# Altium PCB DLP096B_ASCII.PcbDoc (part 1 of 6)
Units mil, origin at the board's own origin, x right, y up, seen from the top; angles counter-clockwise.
Board outline 4950 x 3159.45 mil, 8 copper layers (Top Layer, GND1, SIGNAL1, POWER1, POWER2, SIGNAL2, GND2, Bottom Layer), stack 60.4 mil thick; 327 components, 222 nets, 1374 pads, 853 vias.
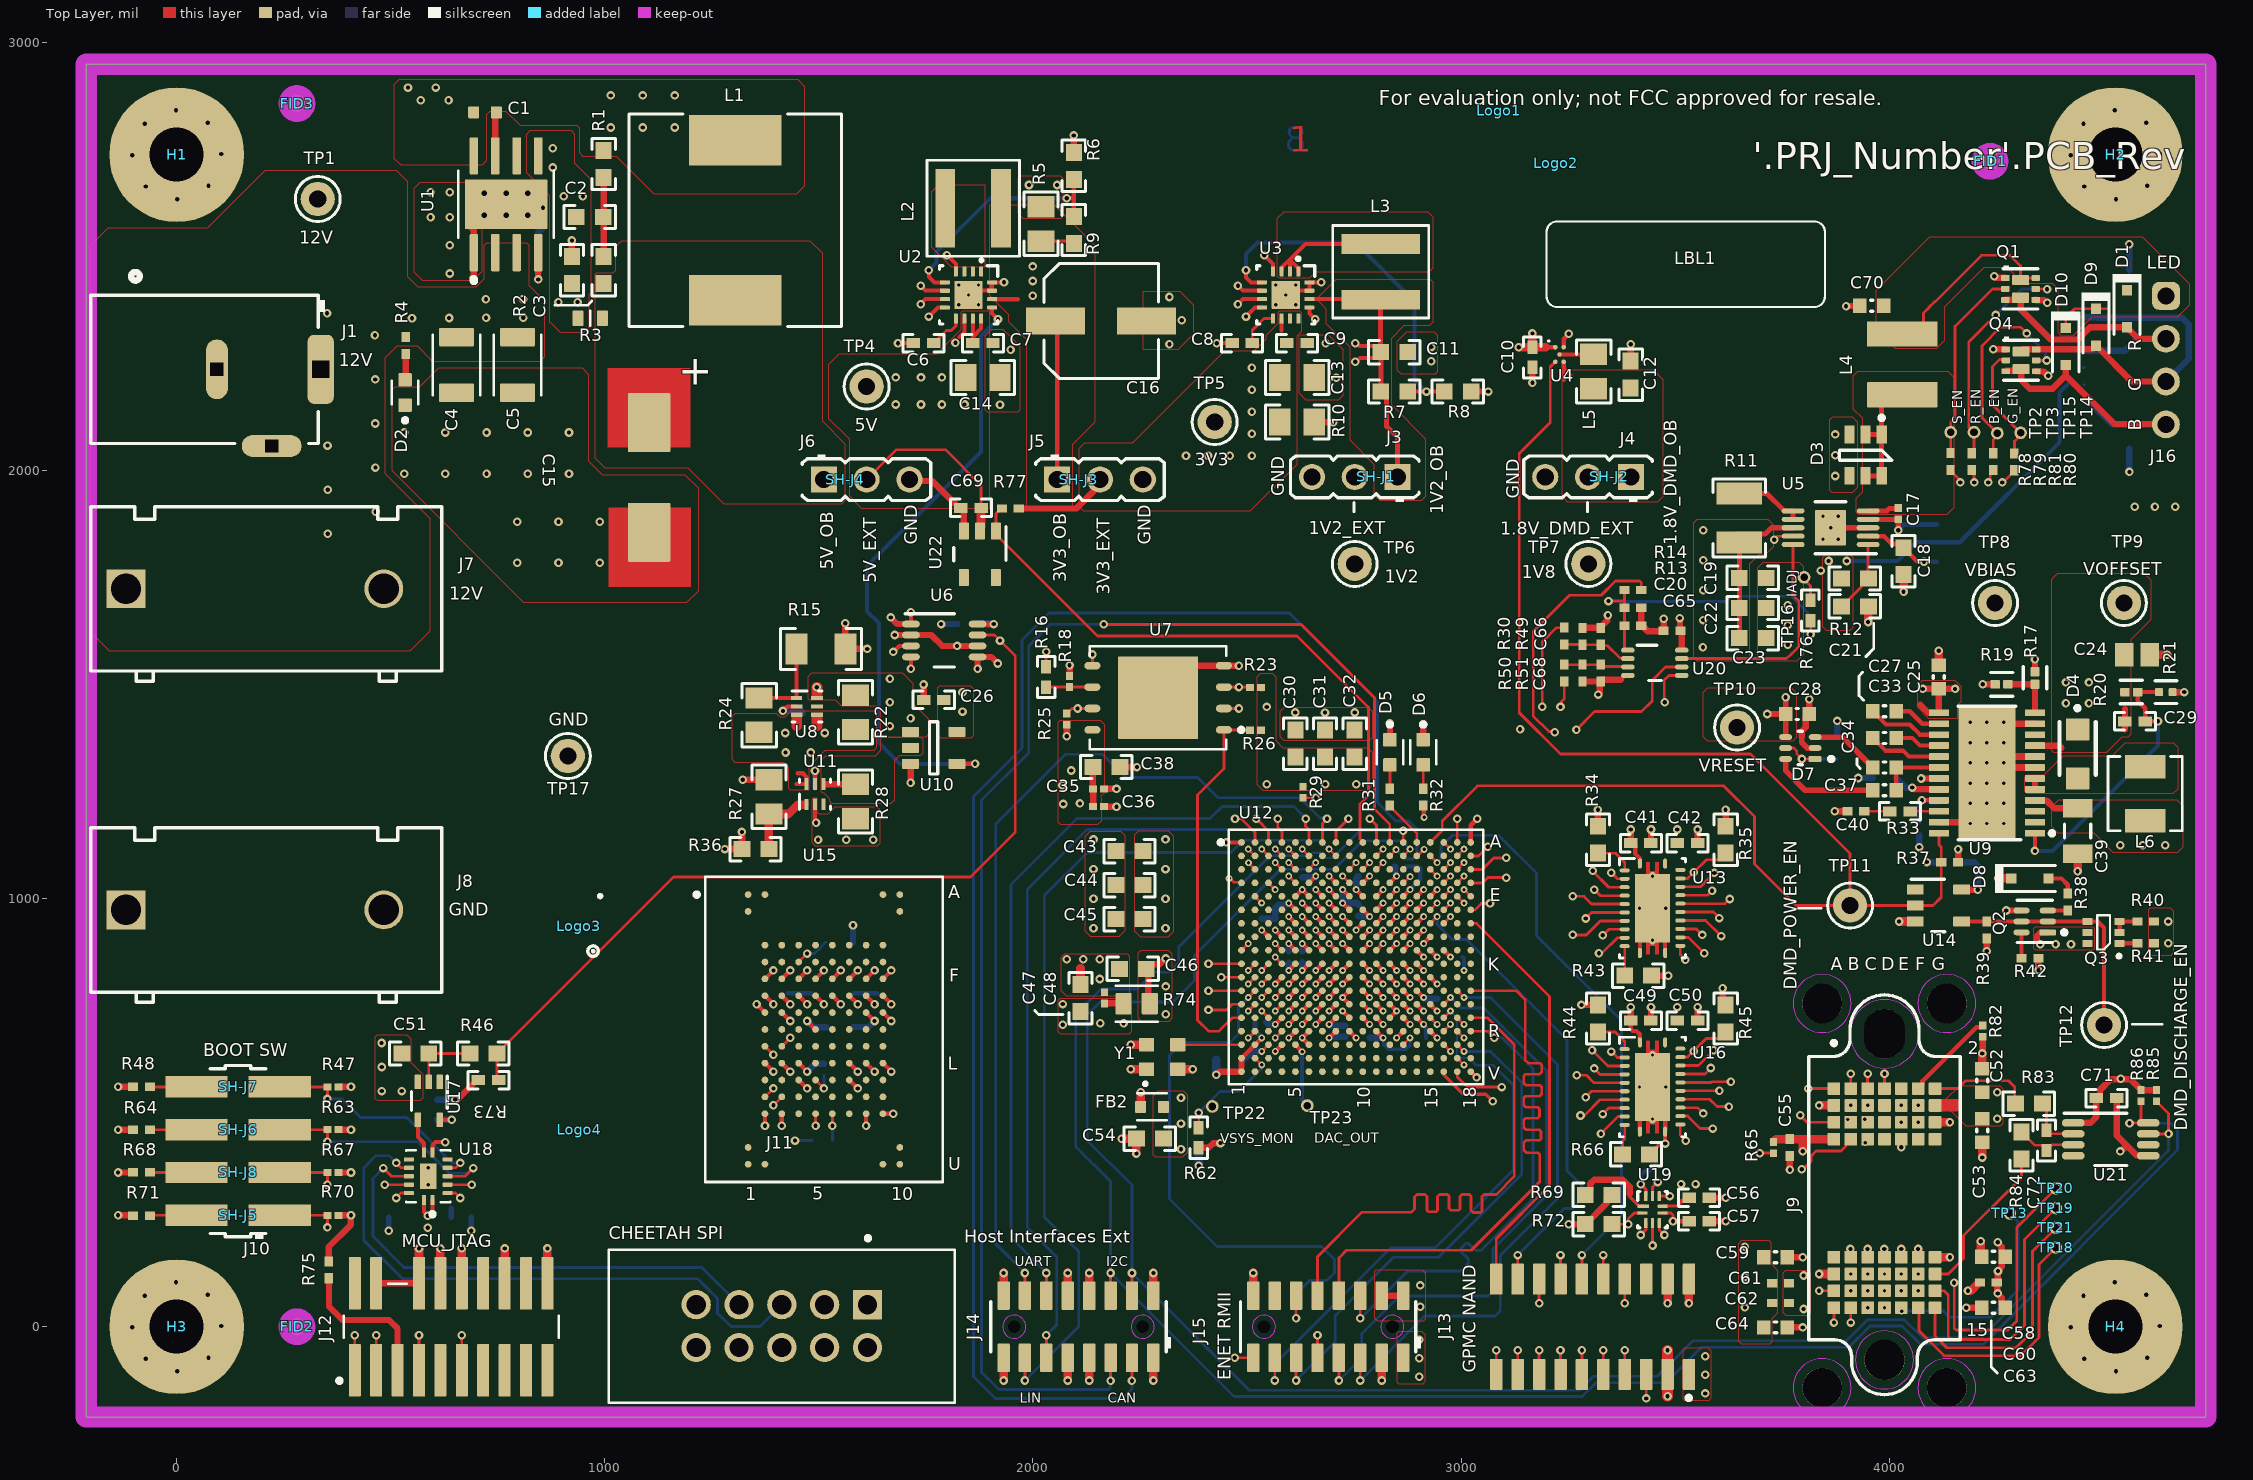
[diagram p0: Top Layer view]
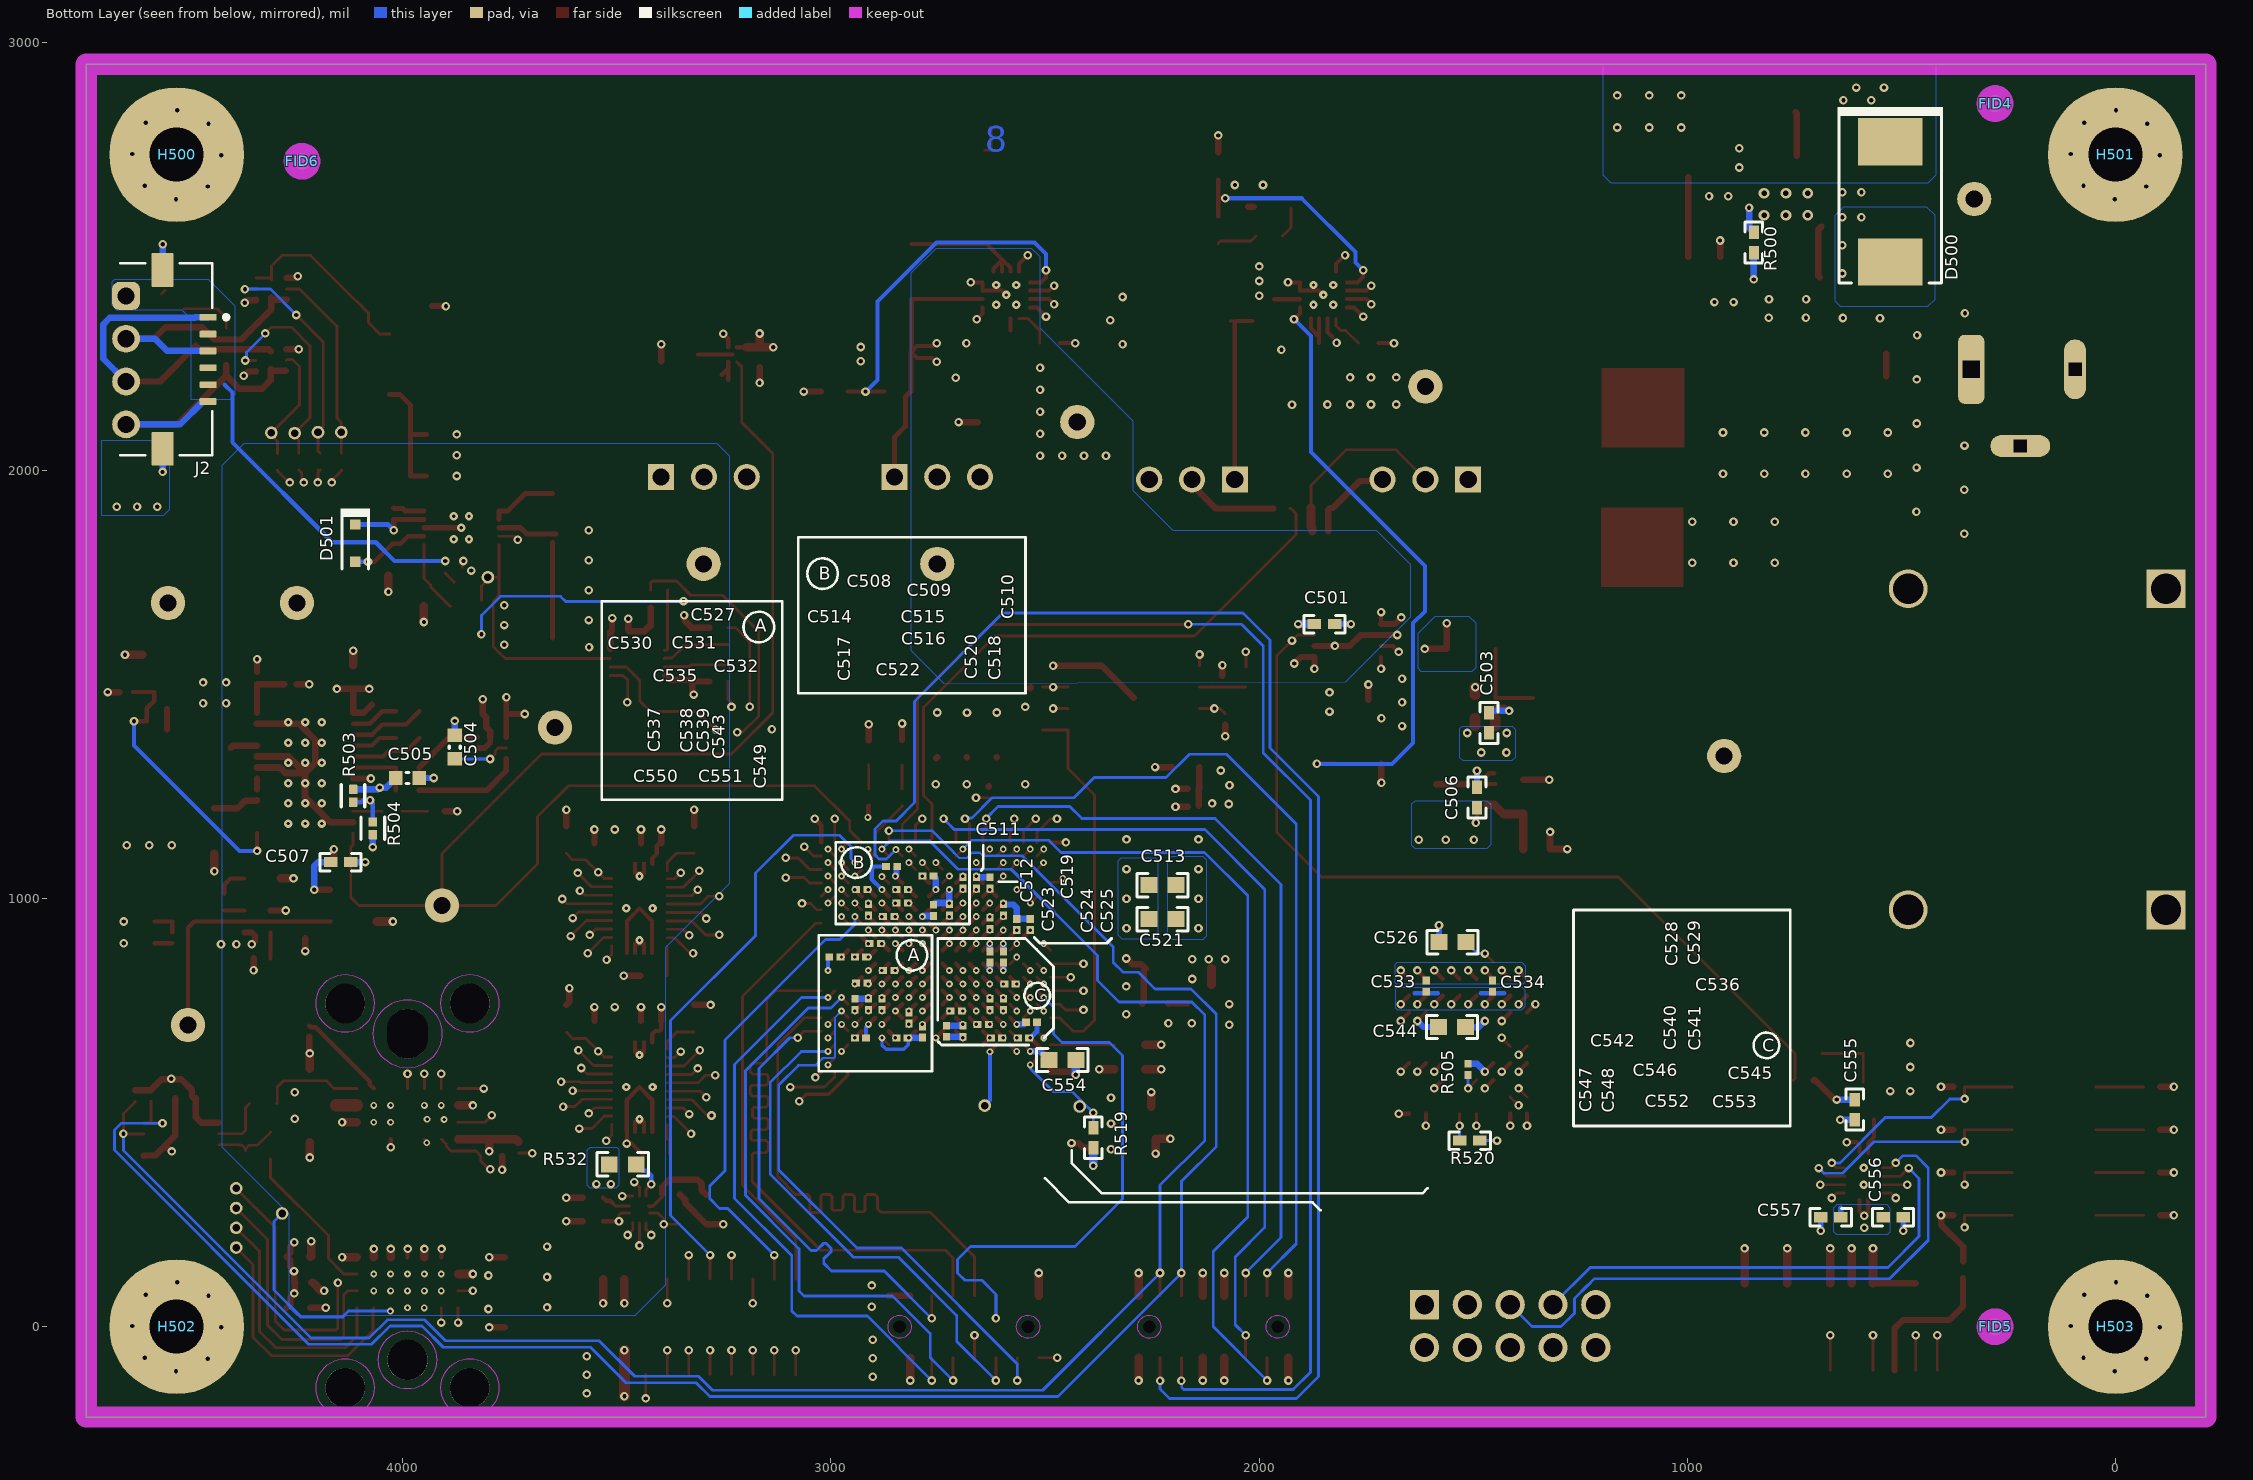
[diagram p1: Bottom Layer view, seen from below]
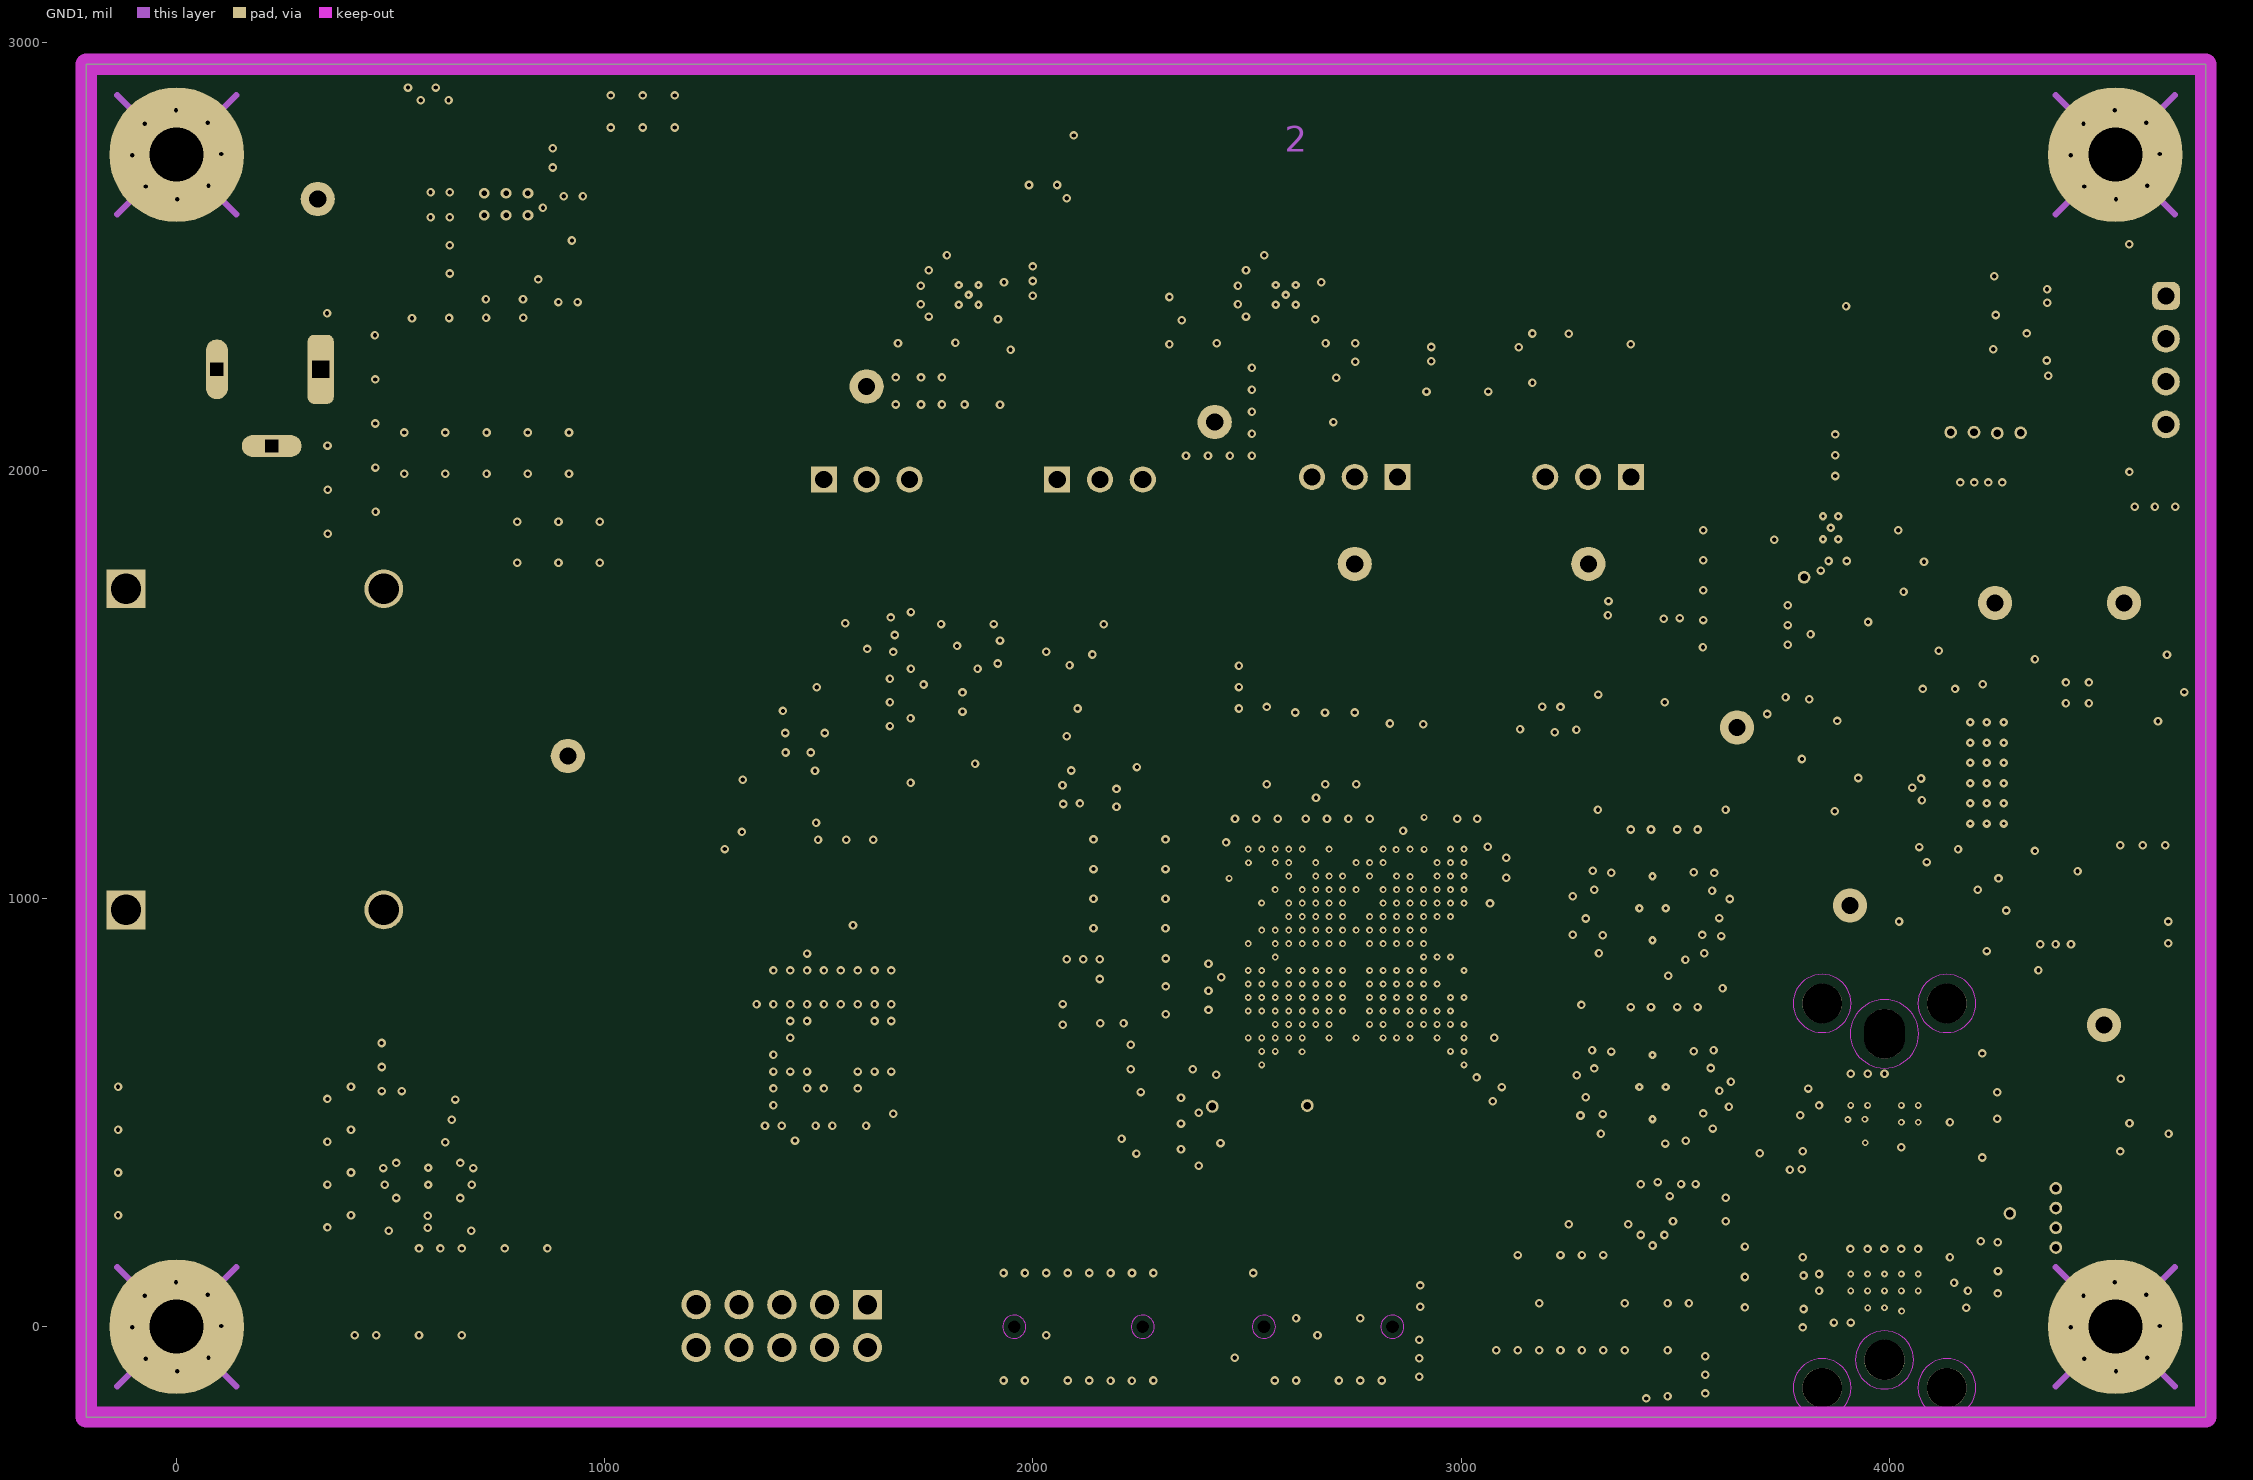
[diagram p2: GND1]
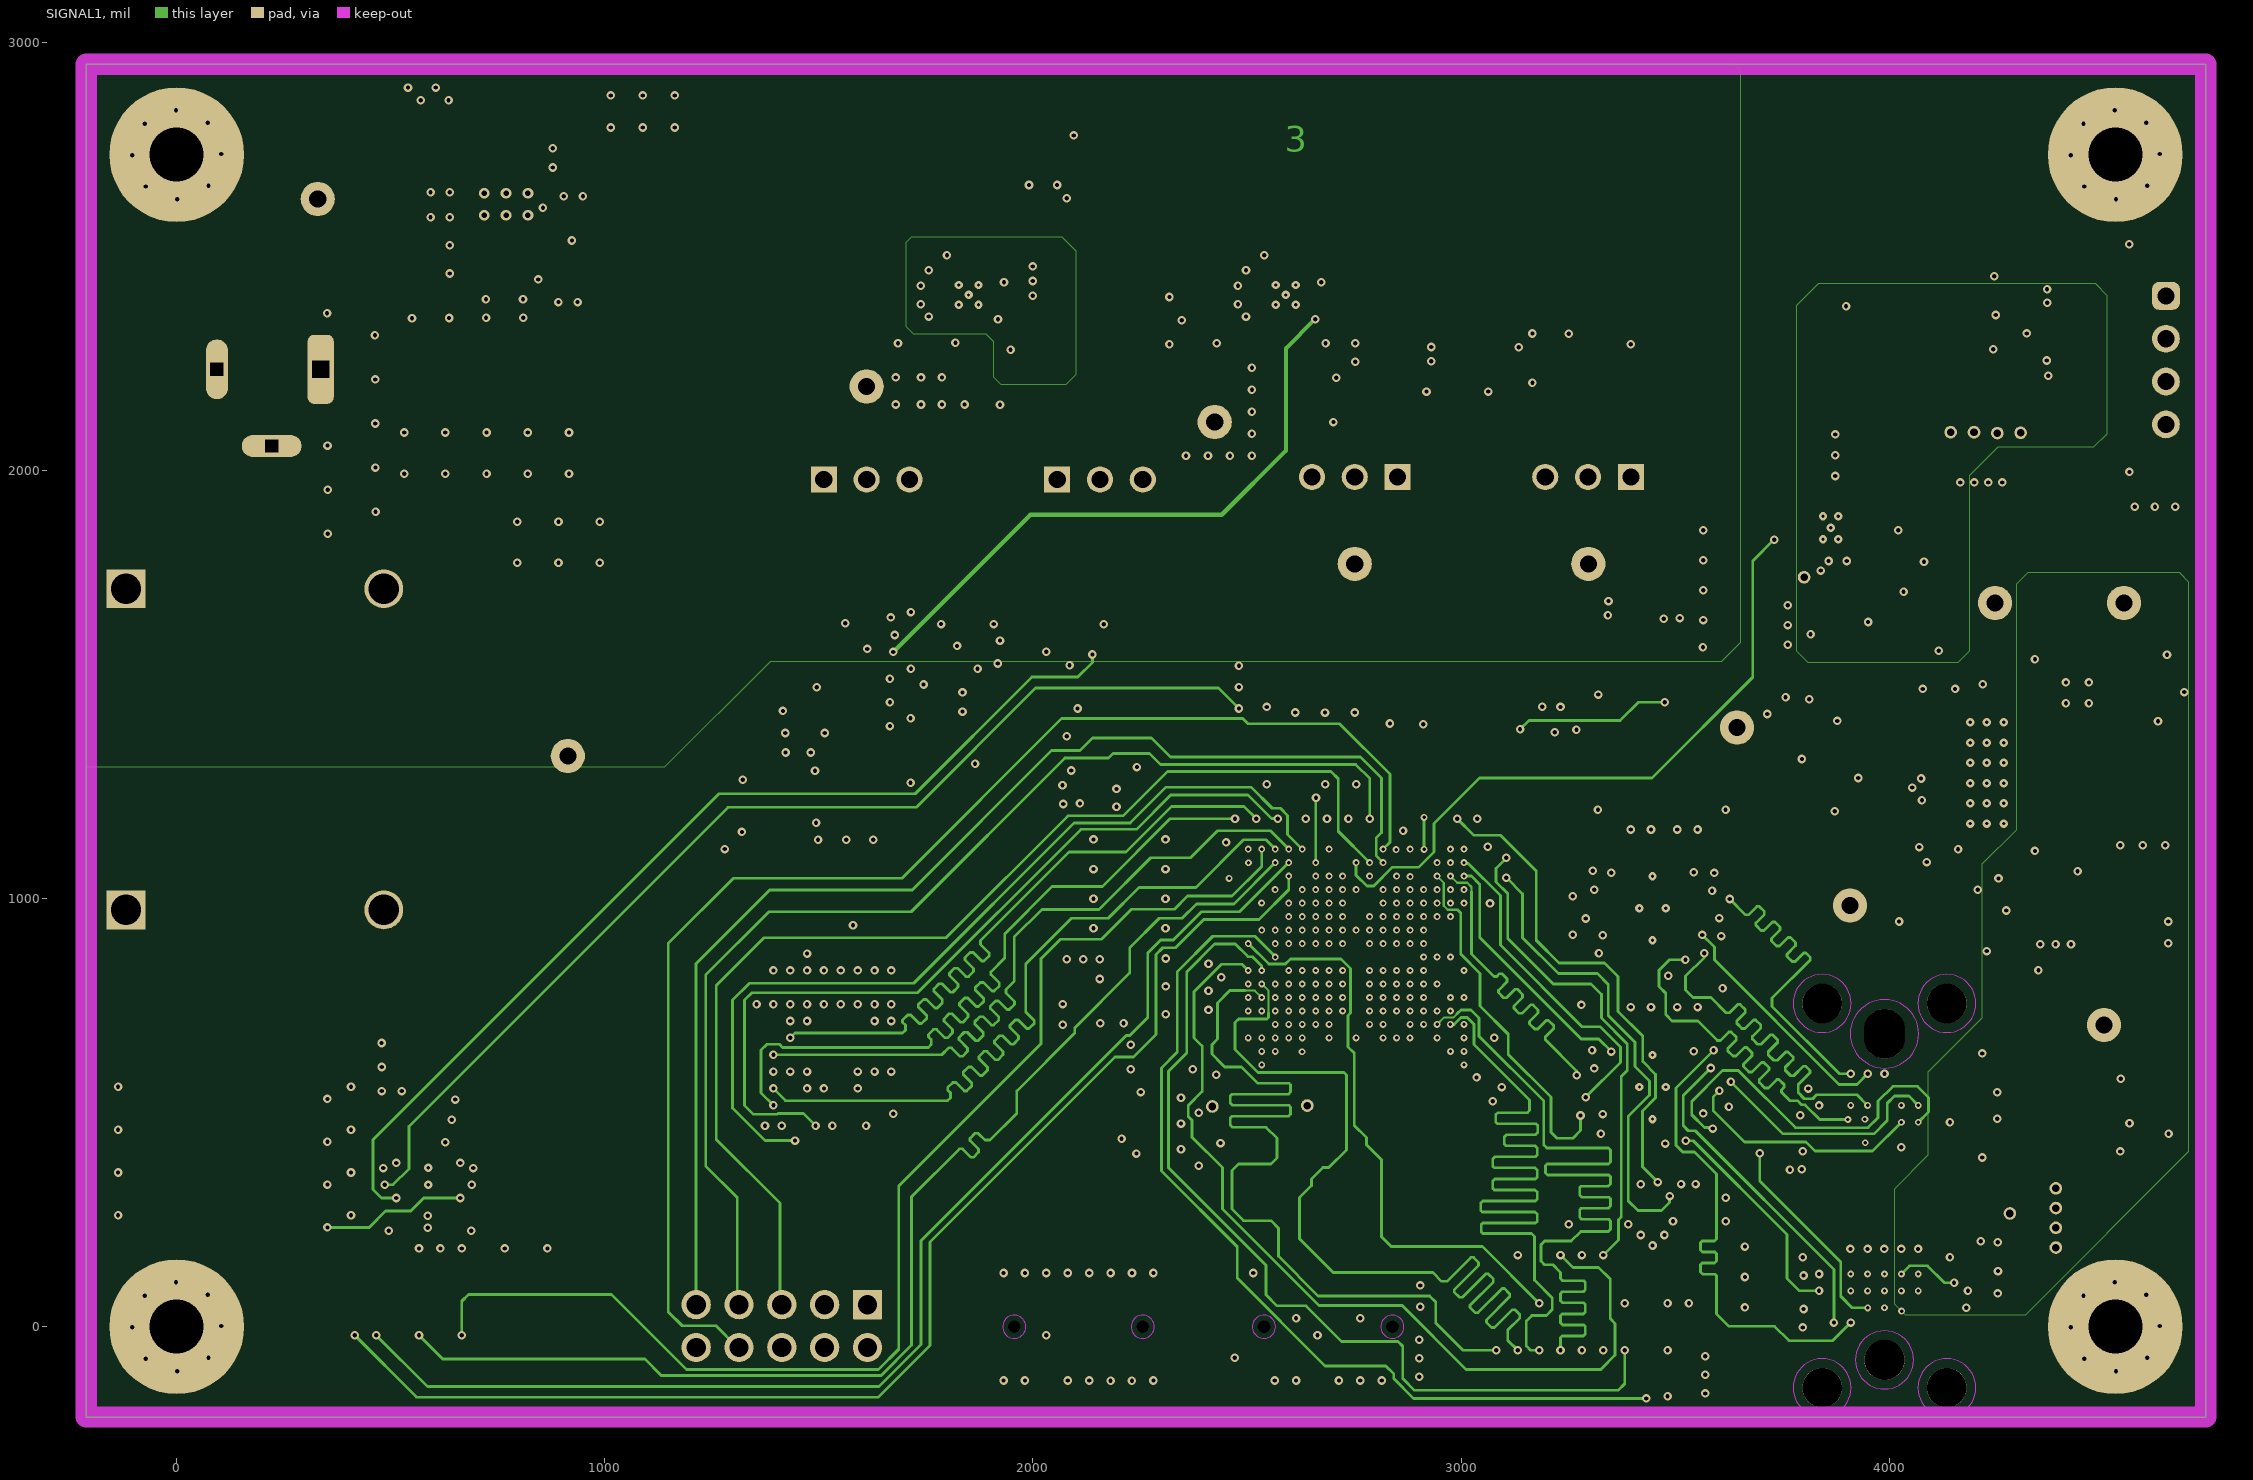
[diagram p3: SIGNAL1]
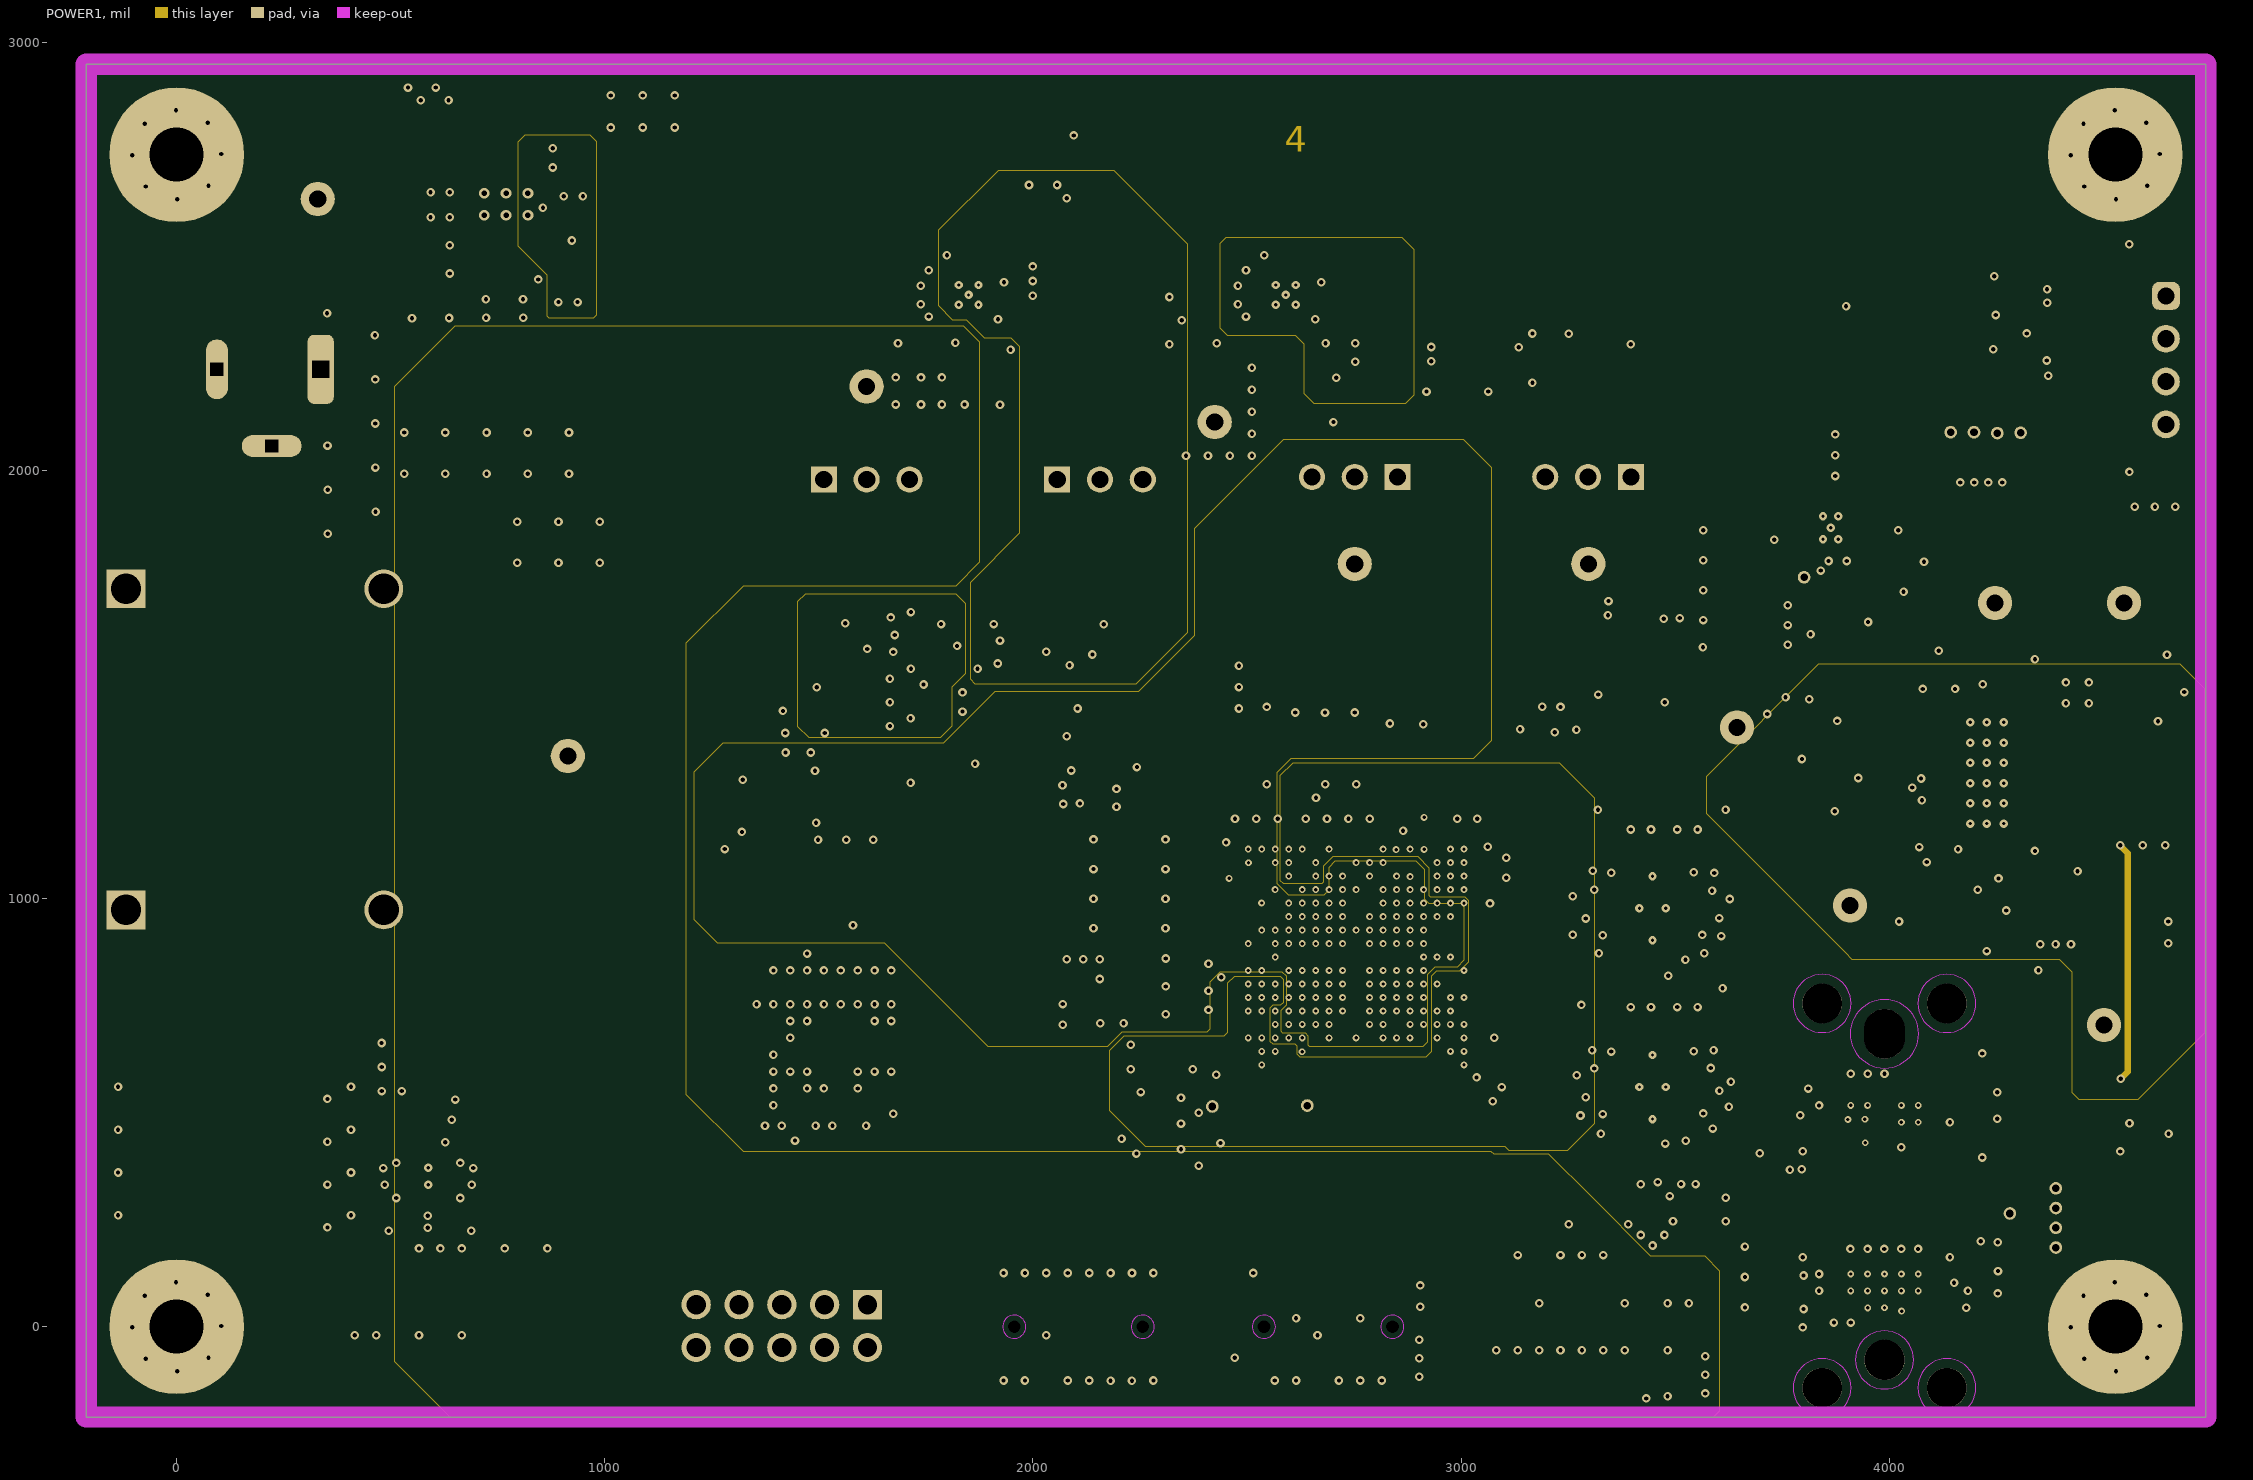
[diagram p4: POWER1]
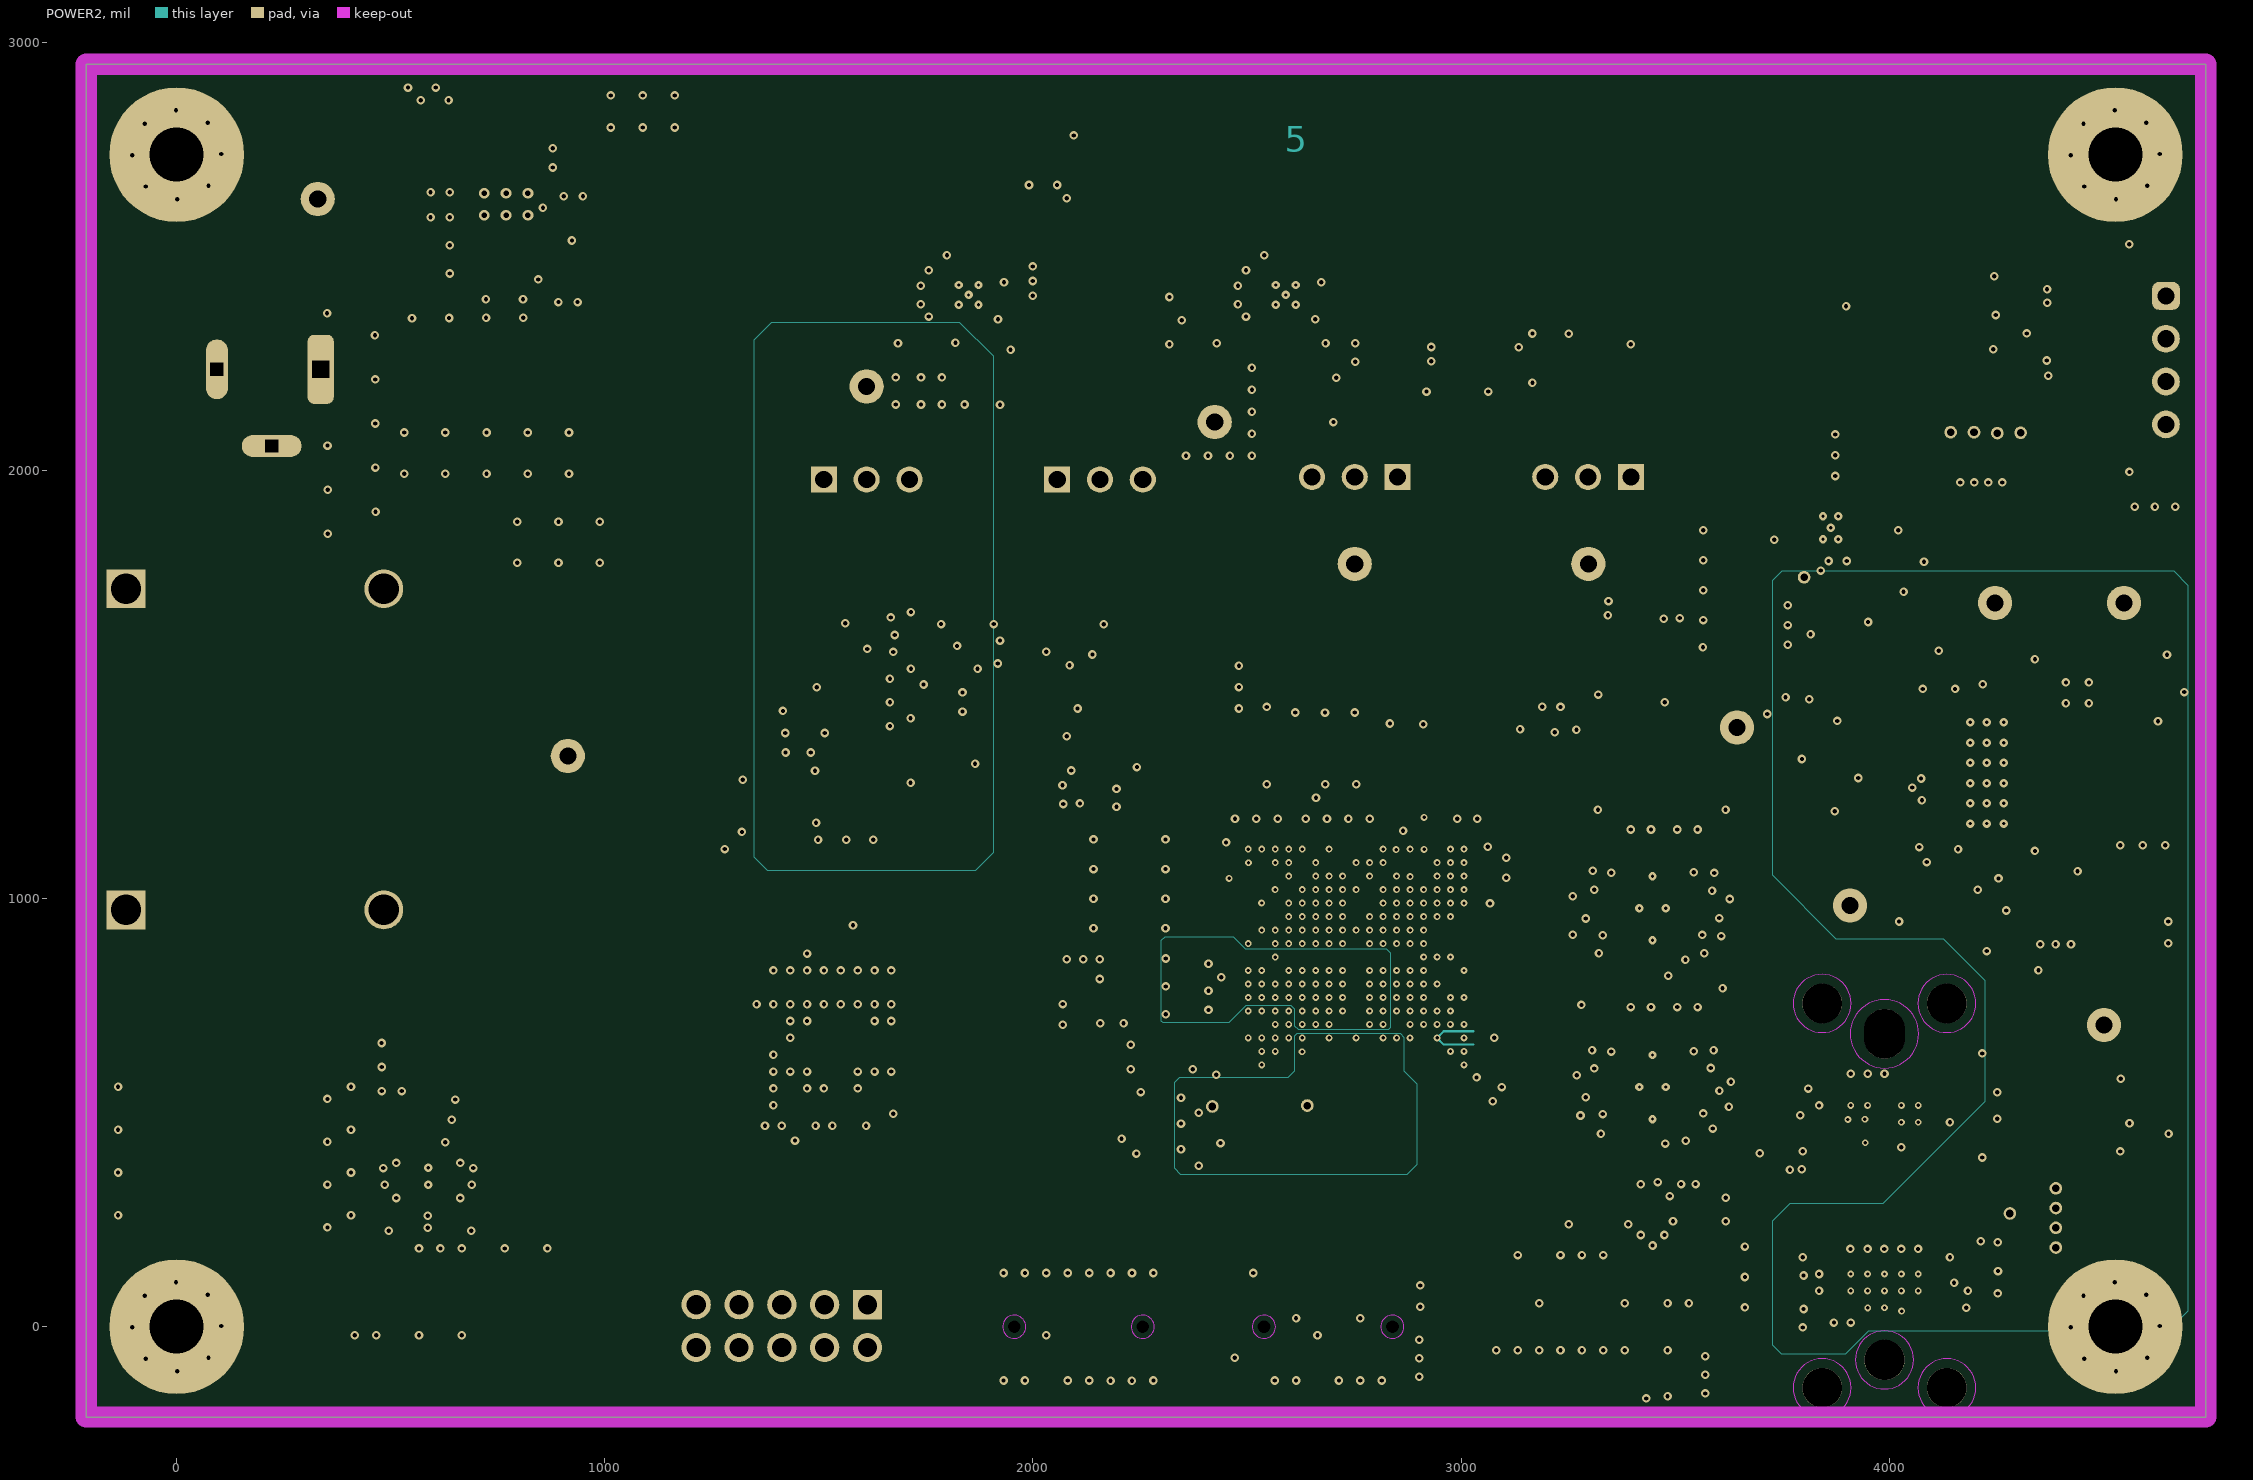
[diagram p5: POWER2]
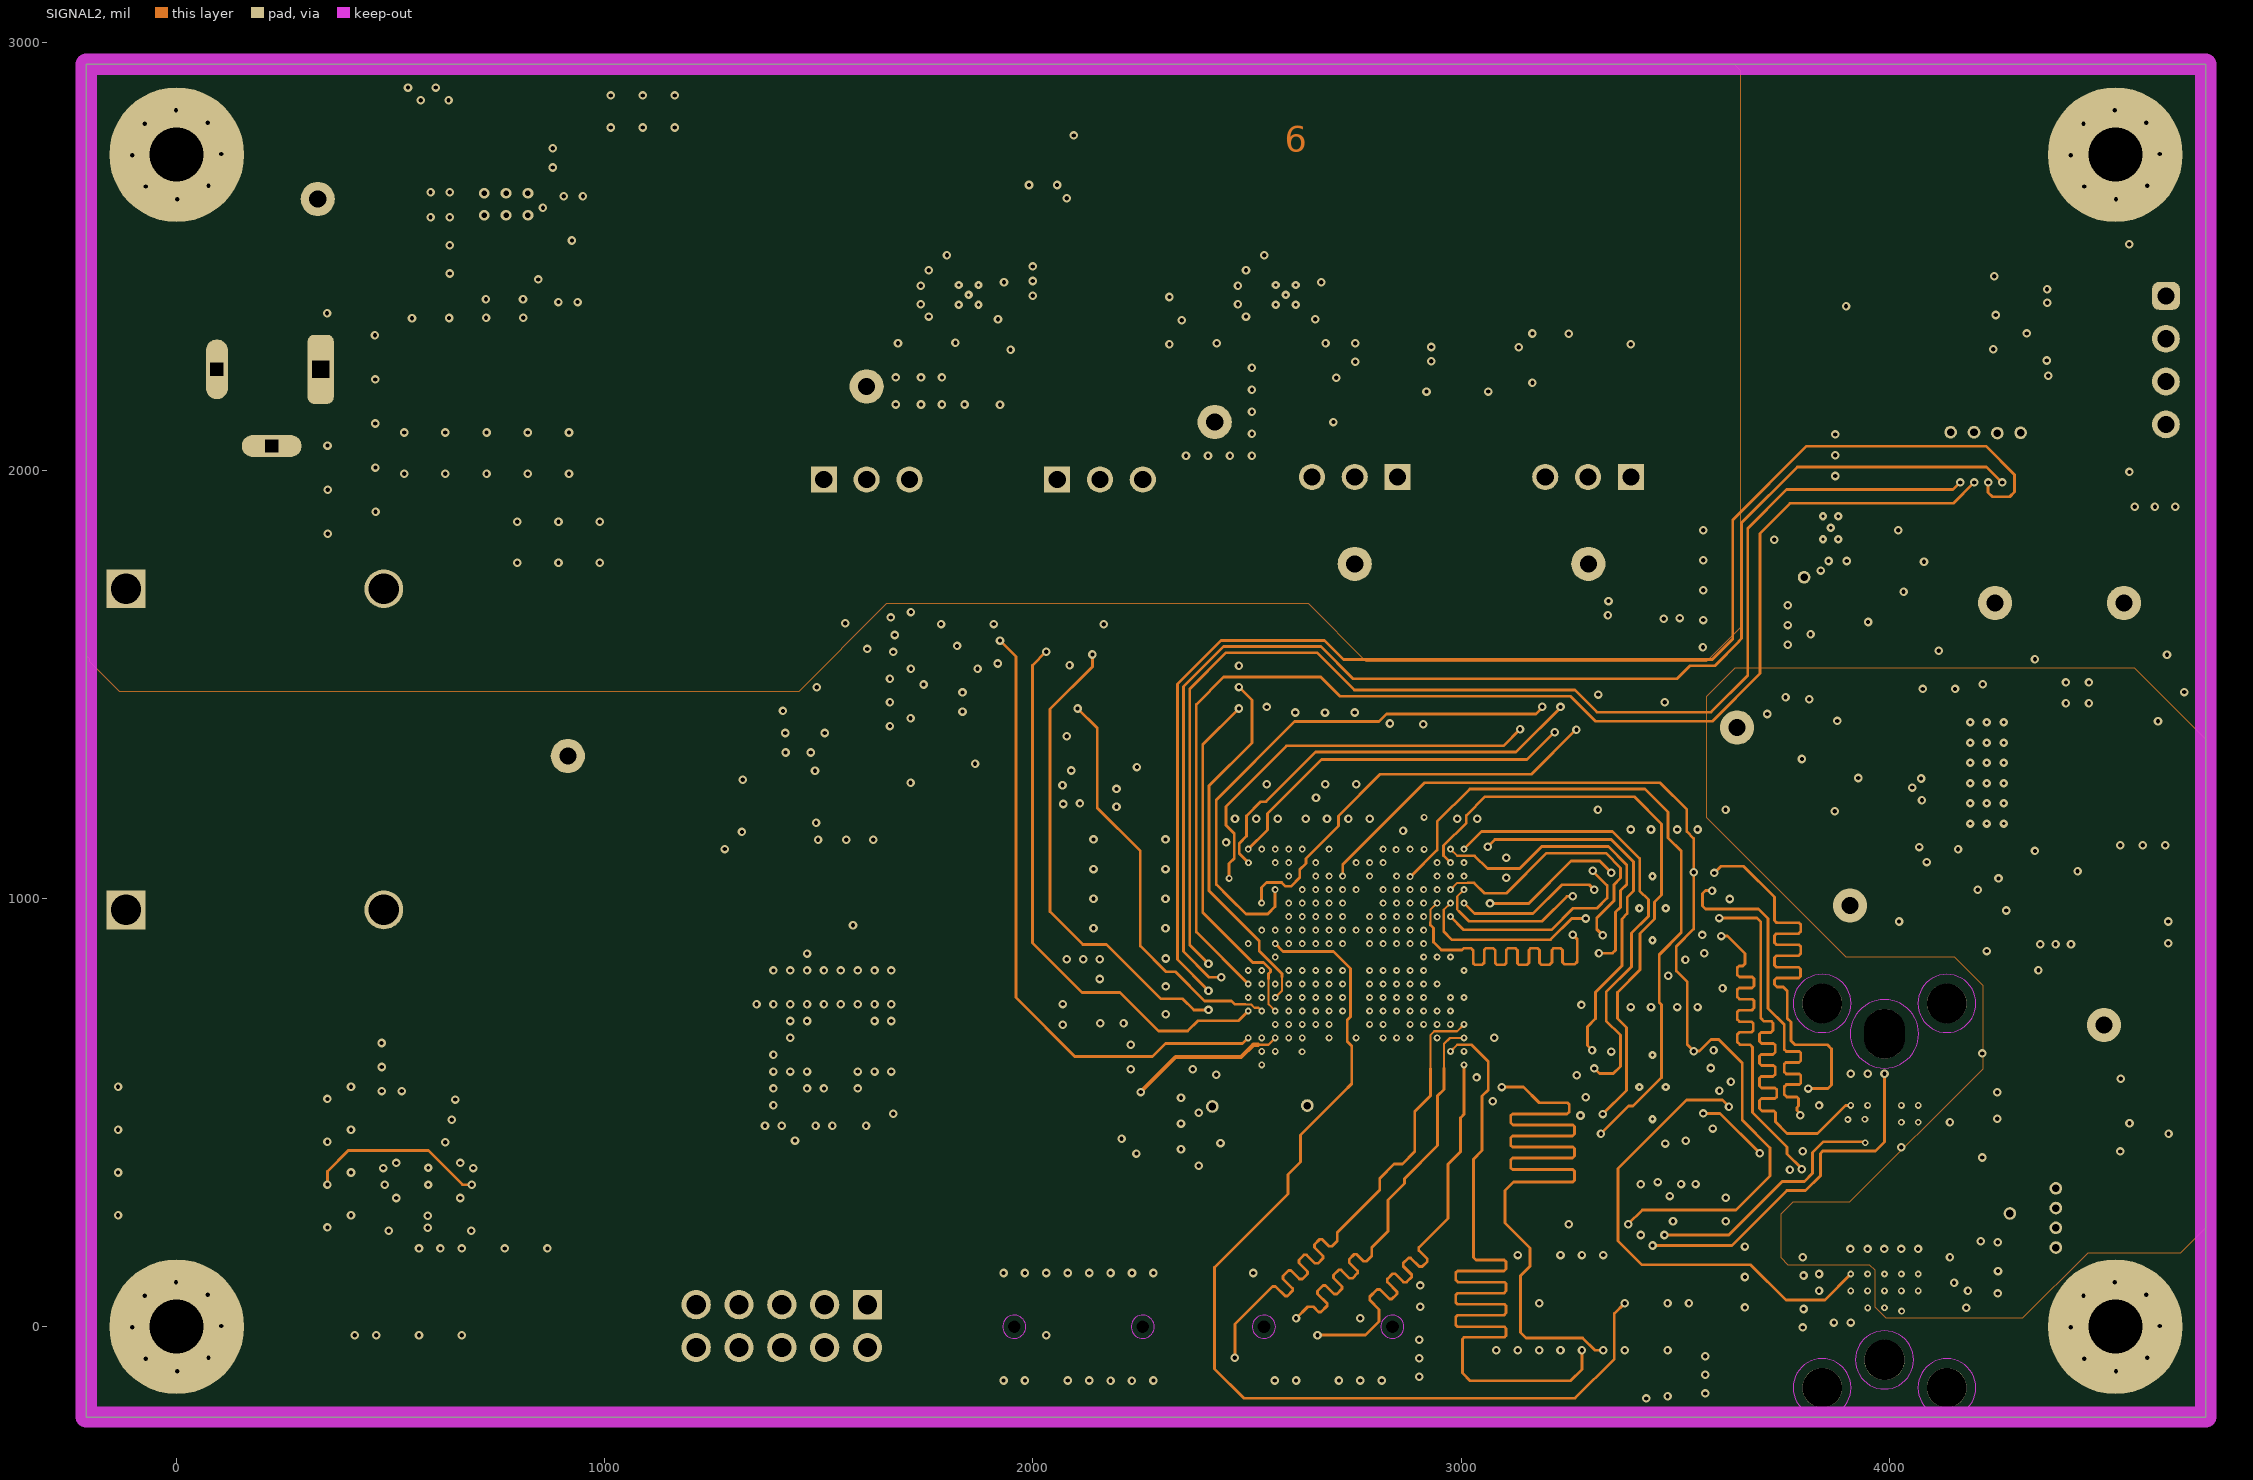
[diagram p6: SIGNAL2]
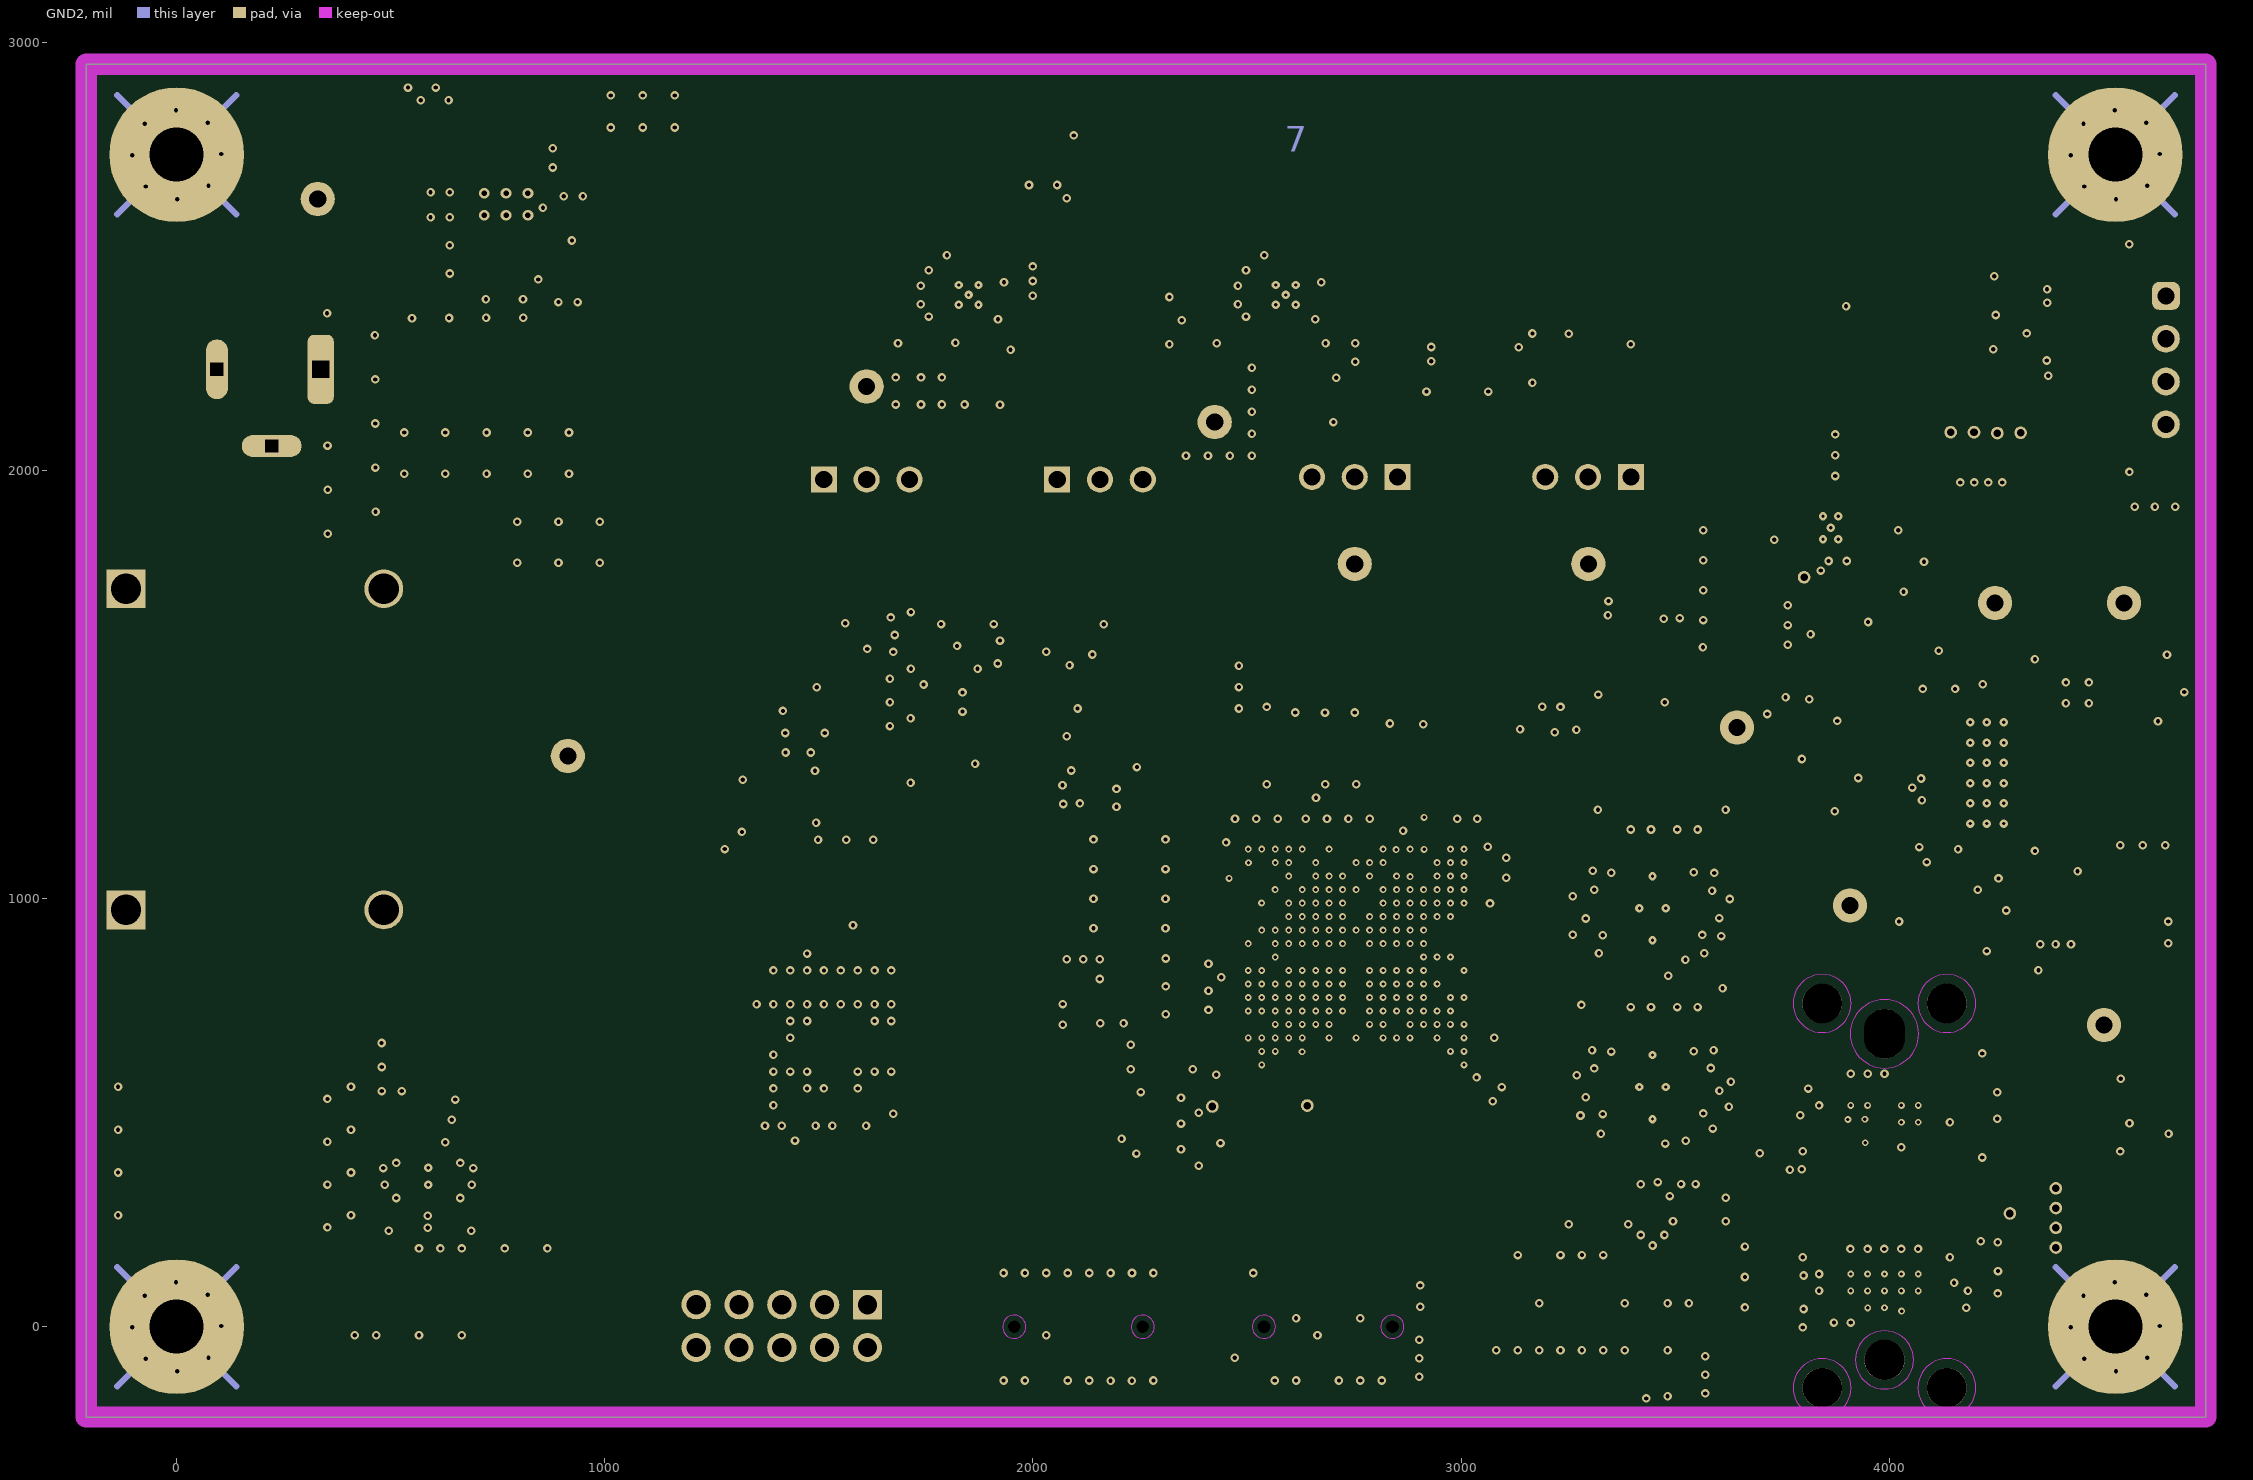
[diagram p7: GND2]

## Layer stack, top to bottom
Top Solder: solder mask 0.8, Solder Resist, Dk 3.5
Top Layer: signal copper 2.8
Dielectric 1: prepreg 4, FR-4 High Tg, Dk 4.1
GND1: signal copper 1.4
Dielectric 2: prepreg 8, FR-4 High Tg, Dk 4.1
SIGNAL1: signal copper 1.4
Dielectric 3: prepreg 8, FR-4 High Tg, Dk 4.1
POWER1: signal copper 1.4
Dielectric 4: core 6.4, FR-4 High Tg, Dk 4.8
POWER2: signal copper 1.4
Dielectric 5: prepreg 8, FR-4 High Tg, Dk 4.1
SIGNAL2: signal copper 1.4
Dielectric 6: prepreg 8, FR-4 High Tg, Dk 4.1
GND2: signal copper 1.4
Dielectric 7: prepreg 4, FR-4 High Tg, Dk 4.1
Bottom Layer: signal copper 2.8
Bottom Solder: solder mask 0.8, Solder Resist, Dk 3.5

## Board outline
-211,-211 4739,-211 4739,2948.45 -211,2948.45

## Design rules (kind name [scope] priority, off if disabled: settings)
AcuteAngle [All] p0: scope1count=1 scope1_0_kind=Board scope1_0_value=Board scope2count=1 scope2_0_kind=Board scope2_0_value=Board commentlength=0 minimum=4.50000000000000E+0001
AcuteAngle [All] p1: minimum=4.50000000000000E+0001 checktracksonly=FALSE
AssemblyTestPointUsage [All] p0: scope1count=1 scope1_0_kind=Board scope1_0_value=Board scope2count=1 scope2_0_kind=Board scope2_0_value=Board commentlength=0
AssemblyTestPointUsage [All] p1: valid=2
AssemblyTestpoint [All] p0: scope1count=1 scope1_0_kind=Board scope1_0_value=Board scope2count=1 scope2_0_kind=Board scope2_0_value=Board commentlength=0
BoardOutlineClearance BoardOutlineClearance_Poly [All] p0 off: scope1count=1 scope1_0_kind=Board scope1_0_value=Board scope2count=1 scope2_0_kind=Board scope2_0_value=Board commentlength=58 gap=25 // Protel DXP Scope 1 Expression Was: OnCopper and IsPoly
BoardOutlineClearance BoardOutlineClearance_MountingHoles [All] p0 off: scope1count=1 scope1_0_kind=Board scope1_0_value=Board scope2count=1 scope2_0_kind=Board scope2_0_value=Board commentlength=86 gap=39.37 // Protel DXP Scope 1 Expression Was: OnCopper and InComponentClass('Mounting Holes')
BoardOutlineClearance BoardOutlineClearance_MountingHoles [OnCopper and InComponentClass('Mounting Holes')] p1: gap=39.37 ignorepadtopadclearanceinfootprint=FALSE
BoardOutlineClearance BoardOutlineClearance_Poly [OnCopper and IsPoly] p2: gap=25 ignorepadtopadclearanceinfootprint=FALSE
Clearance "Clearance_Keepout to all" [All] p0 off: scope1count=1 scope1_0_kind=Board scope1_0_value=Board scope2count=1 scope2_0_kind=Board scope2_0_value=Board commentlength=48 gap=1 // Protel DXP Scope 1 Expression Was: isKeepout
Clearance "Clearance_GND layer" [All] p0 off: scope1count=1 scope1_0_kind=Board scope1_0_value=Board scope2count=1 scope2_0_kind=Board scope2_0_value=Board commentlength=64 gap=8 // Protel DXP Scope 1 Expression Was: InLayerClass('GND_Layer')
Clearance "Clearance_Poly to Poly" [All] p0 off: scope1count=1 scope1_0_kind=Board scope1_0_value=Board scope2count=1 scope2_0_kind=Board scope2_0_value=Board commentlength=48 gap=15 // Protel DXP Scope 2 Expression Was: InPolygon
Clearance Clearance_Voltage [All] p0 off: scope1count=1 scope1_0_kind=Board scope1_0_value=Board scope2count=1 scope2_0_kind=Board scope2_0_value=Board commentlength=97 gap=15 // Protel DXP Scope 1 Expression Was: not WithinRoom('RoomDefinition') and InNetClass('Voltage')
Clearance Clearance_Room1 [All] p0 off: scope1count=1 scope1_0_kind=Board scope1_0_value=Board scope2count=1 scope2_0_kind=Board scope2_0_value=Board commentlength=69 gap=5 // Protel DXP Scope 1 Expression Was: WithinRoom('RoomDefinition_1')
Clearance [All] p0: scope1count=1 scope1_0_kind=Board scope1_0_value=Board scope2count=1 scope2_0_kind=Board scope2_0_value=Board commentlength=0 gap=7.87
Clearance Clearance_FiducialMark [All] p0 off: scope1count=1 scope1_0_kind=Board scope1_0_value=Board scope2count=1 scope2_0_kind=Board scope2_0_value=Board commentlength=81 gap=0 // Protel DXP Scope 2 Expression Was: IsPad and InComponentClass('FiducialMark')
Clearance "Clearance_Poly to All" [All] p0 off: scope1count=1 scope1_0_kind=Board scope1_0_value=Board scope2count=1 scope2_0_kind=Board scope2_0_value=Board commentlength=48 gap=10 // Protel DXP Scope 1 Expression Was: InPolygon
Clearance Clearance_FiducialMark [IsKeepOut and InComponentClass('FiducialMark') vs IsPad and InComponentClass('FiducialMark')] p1: gap=0 ignorepadtopadclearanceinfootprint=FALSE
Clearance "Clearance_Keepout to all" [isKeepout] p2: gap=1 ignorepadtopadclearanceinfootprint=FALSE
Clearance Clearance_Room1 [WithinRoom('RoomDefinition_1')] p3: gap=5 ignorepadtopadclearanceinfootprint=FALSE
Clearance Clearance_Voltage [not WithinRoom('RoomDefinition') and InNetClass('Voltage')] p4: gap=15 ignorepadtopadclearanceinfootprint=FALSE
Clearance "Clearance_GND layer" [InLayerClass('GND_Layer')] p5: gap=8 ignorepadtopadclearanceinfootprint=FALSE
Clearance "Clearance_Poly to Poly" [InPolygon vs InPolygon] p6: gap=15 ignorepadtopadclearanceinfootprint=FALSE
Clearance "Clearance_Poly to All" [InPolygon] p7: gap=10 ignorepadtopadclearanceinfootprint=FALSE
Clearance [All] p8: gap=7.87 ignorepadtopadclearanceinfootprint=FALSE
ComponentClearance [All] p0: scope1count=1 scope1_0_kind=Board scope1_0_value=Board scope2count=1 scope2_0_kind=Board scope2_0_value=Board commentlength=0 gap=10 collisioncheckmode=3
ComponentClearance ComponentClearance_THtoTH [All] p0 off: scope1count=1 scope1_0_kind=Board scope1_0_value=Board scope2count=1 scope2_0_kind=Board scope2_0_value=Board commentlength=54 gap=10 collisioncheckmode=3 // Protel DXP Scope 2 Expression Was: IsThruComponent
ComponentClearance ComponentClearance_THtoSMT [All] p0 off: scope1count=1 scope1_0_kind=Board scope1_0_value=Board scope2count=1 scope2_0_kind=Board scope2_0_value=Board commentlength=53 gap=10 collisioncheckmode=3 // Protel DXP Scope 2 Expression Was: IsSMTComponent
ComponentClearance ComponentClearance_SmallPassives [All] p0 off: scope1count=1 scope1_0_kind=Board scope1_0_value=Board scope2count=1 scope2_0_kind=Board scope2_0_value=Board commentlength=508 gap=10 collisioncheckmode=3 // Protel DXP Scope 2 Expression Was: HasFootprint('0201*') or HasFootprint('0402*') or HasFootprint('0508') or HasFootprint('0603*') or HasFootprint('0612') or HasFootprint('0805*') or HasFootprint('0815*') or HasFootprint('0830*') or HasFootprint('1206*') or HasFootprint('1210*') or HasFootprint('1808*') or HasFootprint('1812*') or HasFootprint('1825*') or HasFootprint('2010*') or HasFootprint('2220*') or HasFootprint('2225*') or HasFootprint('2512*') or HasFootprint('2728*') or HasFootprint('3518*')
ComponentClearance ComponentClearance_MountingHoles [All] p0: scope1count=1 scope1_0_kind=ComponentClass scope1_0_value="Mounting Holes" scope2count=1 scope2_0_kind=Board scope2_0_value=Board commentlength=0 gap=100 collisioncheckmode=3
ComponentClearance ComponentClearance_ScrewToNut [All] p0 off: scope1count=1 scope1_0_kind=Board scope1_0_value=Board scope2count=1 scope2_0_kind=Board scope2_0_value=Board commentlength=71 gap=5 collisioncheckmode=3 // Protel DXP Scope 2 Expression Was: (HasFootprint('Keystone_1902C'))
ComponentClearance ComponentClearance_Logo [All] p0: scope1count=1 scope1_0_kind=ComponentClass scope1_0_value=Logo scope2count=1 scope2_0_kind=Board scope2_0_value=Board commentlength=0 gap=10 collisioncheckmode=3
ComponentClearance ComponentClearance_Shunt [All] p0: scope1count=1 scope1_0_kind=ComponentClass scope1_0_value=Header scope2count=1 scope2_0_kind=ComponentClass scope2_0_value=Shunt commentlength=0 gap=0 collisioncheckmode=3
ComponentClearance ComponentClearance_MountingHoles_FiducialMarks [All] p0: scope1count=1 scope1_0_kind=ComponentClass scope1_0_value="Mounting Holes" scope2count=1 scope2_0_kind=ComponentClass scope2_0_value=FiducialMark commentlength=0 gap=10 collisioncheckmode=3
ComponentClearance ComponentClearance_MountingHoles_FiducialMarks [InComponentClass('Mounting Holes') vs InComponentClass('FiducialMark')] p1: gap=10 collisioncheckmode=3 verticalgap=10 showdistances=FALSE
ComponentClearance ComponentClearance_Shunt [InComponentClass('Header') vs InComponentClass('Shunt')] p2: gap=0 collisioncheckmode=3 verticalgap=0 showdistances=FALSE
ComponentClearance ComponentClearance_Logo [InComponentClass('Logo')] p3: gap=10 collisioncheckmode=3 verticalgap=10 showdistances=FALSE
ComponentClearance ComponentClearance_ScrewToNut [(HasFootprint('NY PMS 440 0025 PH')) vs (HasFootprint('Keystone_1902C'))] p4: gap=5 collisioncheckmode=3 verticalgap=10 showdistances=FALSE
ComponentClearance ComponentClearance_MountingHoles [InComponentClass('Mounting Holes')] p5: gap=100 collisioncheckmode=3 verticalgap=100000 showdistances=FALSE
ComponentClearance ComponentClearance_SmallPassives [HasFootprint('0201*') or HasFootprint('0402*') or HasFootprint('0508') or HasFootprint('0603*') or HasFootprint('0612') or HasFootprint('0805*') or HasFootprint('0815*') or HasFootprint('0830*') or HasFootprint('1206*') or HasFootprint('1210*') or HasFootprint('1808*') or HasFootprint('1812*') or HasFootprint('1825*') or HasFootprint('2010*') or HasFootprint('2220*') or HasFootprint('2225*') or HasFootprint('2512*') or HasFootprint('2728*') or HasFootprint('3518*') vs HasFootprint('0201*') or HasFootprint('0402*') or HasFootprint('0508') or HasFootprint('0603*') or HasFootprint('0612') or HasFootprint('0805*') or HasFootprint('0815*') or HasFootprint('0830*') or HasFootprint('1206*') or HasFootprint('1210*') or HasFootprint('1808*') or HasFootprint('1812*') or HasFootprint('1825*') or HasFootprint('2010*') or HasFootprint('2220*') or HasFootprint('2225*') or HasFootprint('2512*') or HasFootprint('2728*') or HasFootprint('3518*')] p6: gap=10 collisioncheckmode=3 verticalgap=10 showdistances=FALSE
ComponentClearance ComponentClearance_THtoSMT [IsThruComponent vs IsSMTComponent] p7: gap=10 collisioncheckmode=3 verticalgap=30 showdistances=FALSE
ComponentClearance ComponentClearance_THtoTH [IsThruComponent vs IsThruComponent] p8: gap=10 collisioncheckmode=3 verticalgap=30 showdistances=FALSE
ComponentClearance [All] p9: gap=10 collisioncheckmode=3 verticalgap=10 showdistances=FALSE
DiffPairsRouting [All] p0: scope1count=1 scope1_0_kind=Board scope1_0_value=Board scope2count=1 scope2_0_kind=Board scope2_0_value=Board commentlength=0
DiffPairsRouting [All] p1: maxlimit=100 minlimit=10 mostfreqgap=10 toplayer_minwidth=15 toplayer_maxwidth=15 toplayer_prefwidth=15 midlayer1_minwidth=15 midlayer1_maxwidth=15 midlayer1_prefwidth=15 midlayer2_minwidth=15 midlayer2_maxwidth=15 midlayer2_prefwidth=15 midlayer3_minwidth=15 midlayer3_maxwidth=15 midlayer3_prefwidth=15 midlayer4_minwidth=15 midlayer4_maxwidth=15 midlayer4_prefwidth=15 midlayer5_minwidth=15 midlayer5_maxwidth=15 midlayer5_prefwidth=15 midlayer6_minwidth=15 midlayer6_maxwidth=15 midlayer6_prefwidth=15 bottomlayer_minwidth=15 bottomlayer_maxwidth=15 bottomlayer_prefwidth=15 maxuncoupledlength=1000
FabricationTestPointUsage TestPointUsage [All] p0: scope1count=1 scope1_0_kind=Board scope1_0_value=Board scope2count=1 scope2_0_kind=Board scope2_0_value=Board commentlength=0 valid=2 allowmultiple=FALSE
FabricationTestPointUsage TestPointUsage [All] p1: valid=2 allowmultiple=FALSE
FabricationTestpoint Testpoint [All] p0: scope1count=1 scope1_0_kind=Board scope1_0_value=Board scope2count=1 scope2_0_kind=Board scope2_0_value=Board commentlength=0 side=3 testpointundercomponent=TRUE minsize=40 maxsize=100 preferedsize=60 minholesize=0 maxholesize=40 preferedholesize=32 testpointgrid=1
FabricationTestpoint Testpoint [All] p1: side=3 testpointundercomponent=TRUE minsize=40 maxsize=100 preferedsize=60 minholesize=0 maxholesize=40 preferedholesize=32 testpointgrid=1 allowsidetop=TRUE allowsidebottom=TRUE usegrid=TRUE gridtolerance=0.01
FanoutControl Fanout_Small [All] p0 off: scope1count=1 scope1_0_kind=Board scope1_0_value=Board scope2count=1 scope2_0_kind=Board scope2_0_value=Board commentlength=84 // Protel DXP Scope 1 Expression Was: (CompPinCount < 5)   Fanout_Small (Default Rule)
FanoutControl Fanout_Default [All] p0: scope1count=1 scope1_0_kind=Board scope1_0_value=Board scope2count=1 scope2_0_kind=Board scope2_0_value=Board commentlength=30 // Fanout_Default (Default Rule)
FanoutControl Fanout_SOIC [All] p0 off: scope1count=1 scope1_0_kind=Board scope1_0_value=Board scope2count=1 scope2_0_kind=Board scope2_0_value=Board commentlength=71 // Protel DXP Scope 1 Expression Was: IsSOIC   Fanout_SOIC (Default Rule)
FanoutControl Fanout_BGA [All] p0 off: scope1count=1 scope1_0_kind=Board scope1_0_value=Board scope2count=1 scope2_0_kind=Board scope2_0_value=Board commentlength=69 // Protel DXP Scope 1 Expression Was: IsBGA   Fanout_BGA (Default Rule)
FanoutControl Fanout_LCC [All] p0 off: scope1count=1 scope1_0_kind=Board scope1_0_value=Board scope2count=1 scope2_0_kind=Board scope2_0_value=Board commentlength=69 // Protel DXP Scope 1 Expression Was: IsLCC   Fanout_LCC (Default Rule)
FanoutControl Fanout_LCC [IsLCC] p1: bgadir=Out bgaviamode=Centered fanoutstyle=Auto fanoutdirection=Alternating viagrid=1 // Fanout_LCC (Default Rule)
FanoutControl Fanout_BGA [IsBGA] p2: bgadir=Out bgaviamode=Centered fanoutstyle=Auto fanoutdirection=Alternating viagrid=1 // Fanout_BGA (Default Rule)
FanoutControl Fanout_Default [All] p4: bgadir=Out bgaviamode=Centered fanoutstyle=Auto fanoutdirection=Alternating viagrid=1 // Fanout_Default (Default Rule)
FanoutControl Fanout_Small [(CompPinCount < 5)] p5: bgadir=Out bgaviamode=Centered fanoutstyle=Auto fanoutdirection=OutThenIn viagrid=1 // Fanout_Small (Default Rule)
Height [All] p0: scope1count=1 scope1_0_kind=Board scope1_0_value=Board scope2count=1 scope2_0_kind=Board scope2_0_value=Board commentlength=0
HoleSize [All] p0: scope1count=1 scope1_0_kind=Board scope1_0_value=Board scope2count=1 scope2_0_kind=Board scope2_0_value=Board commentlength=0 absolutevalues=TRUE maxlimit=251 minlimit=7.87 maxpercent=80.000 minpercent=20.000
HoleSize [All] p1: absolutevalues=TRUE maxlimit=251 minlimit=7.87 maxpercent=80.000 minpercent=20.000
HoleToHoleClearance [All] p0: scope1count=1 scope1_0_kind=Board scope1_0_value=Board scope2count=1 scope2_0_kind=Board scope2_0_value=Board commentlength=0
LayerPairs [All] p0: scope1count=1 scope1_0_kind=Board scope1_0_value=Board scope2count=1 scope2_0_kind=Board scope2_0_value=Board commentlength=0 enforce=TRUE
MinimumAnnularRing [All] p0: scope1count=1 scope1_0_kind=Board scope1_0_value=Board scope2count=1 scope2_0_kind=Board scope2_0_value=Board commentlength=0 minimumring=3.9
MinimumAnnularRing MinimumAnnularRing_ThermalPadVias [All] p0 off: scope1count=1 scope1_0_kind=Board scope1_0_value=Board scope2count=1 scope2_0_kind=Board scope2_0_value=Board commentlength=63 minimumring=5.91 // Protel DXP Scope 1 Expression Was: IsVia and InAnyComponent
MinimumAnnularRing MinimumAnnularRing_ThermalPadVias [IsVia and InAnyComponent] p1: minimumring=5.91
MinimumAnnularRing [All] p2: minimumring=3.9
MinimumSolderMaskSliver [All] p0: scope1count=1 scope1_0_kind=Board scope1_0_value=Board scope2count=1 scope2_0_kind=Board scope2_0_value=Board commentlength=0
MinimumSolderMaskSliver MinimumSolderMaskSliver_Logo [All] p0: scope1count=1 scope1_0_kind=ComponentClass scope1_0_value=Logo scope2count=1 scope2_0_kind=ComponentClass scope2_0_value=Logo commentlength=0
MinimumSolderMaskSliver MinimumSolderMaskSliver_Logo [InComponentClass('Logo') vs InComponentClass('Logo')] p1: minsoldermaskwidth=0.7
MinimumSolderMaskSliver [All] p2: minsoldermaskwidth=3.94
NetAntennae [All] p0: scope1count=1 scope1_0_kind=Board scope1_0_value=Board scope2count=1 scope2_0_kind=Board scope2_0_value=Board commentlength=0
PasteMaskExpansion [All] p0: scope1count=1 scope1_0_kind=Board scope1_0_value=Board scope2count=1 scope2_0_kind=Board scope2_0_value=Board commentlength=0 expansion=0
PlaneClearance [All] p0: scope1count=1 scope1_0_kind=Board scope1_0_value=Board scope2count=1 scope2_0_kind=Board scope2_0_value=Board commentlength=0 clearance=20
PlaneConnect [All] p0: scope1count=1 scope1_0_kind=Board scope1_0_value=Board scope2count=1 scope2_0_kind=Board scope2_0_value=Board commentlength=0 planeconnectstyle=Relief reliefexpansion=10 reliefentries=4 reliefconductorwidth=10 reliefairgap=10
PlaneConnect [All] p1: planeconnectstyle=Relief reliefexpansion=10 reliefentries=4 reliefconductorwidth=10 reliefairgap=10
PolygonConnect [All] p0: scope1count=1 scope1_0_kind=Board scope1_0_value=Board scope2count=1 scope2_0_kind=Board scope2_0_value=Board commentlength=0 connectstyle=Relief reliefconductorwidth=15 reliefentries=4 polygonreliefangle="90 Angle"
PolygonConnect [All] p1: thpad.connectstyle=Relief thpad.reliefconductorwidth=15 thpad.reliefentries=4 thpad.polygonreliefangle="90 Angle" thpad.airgapwidth=10 smdpad.connectstyle=Relief smdpad.reliefconductorwidth=15 smdpad.reliefentries=4 smdpad.polygonreliefangle="90 Angle" smdpad.airgapwidth=10 via.connectstyle=Direct via.reliefconductorwidth=10 via.reliefentries=4 via.polygonreliefangle="90 Angle" via.airgapwidth=10
RoomDefinition RoomDefinition_1 [All] p0 off: scope1count=1 scope1_0_kind=Board scope1_0_value=Board scope2count=1 scope2_0_kind=Board scope2_0_value=Board commentlength=44 region_x1=33626388 region_y1=23046254 region_x2=39577892 region_y2=29128956 confinementstyle=ConfineIn // Protel DXP Scope 1 Expression Was: False
RoomDefinition RoomDefinition_1 [False vs False] p1: confinementstyle=ConfineIn formatcopy=TRUE lockcomponents=FALSE outline 2459.64,1167.9 3054.79,1167.9 3054.79,559.63 2459.64,559.63
RoutingCorners [All] p0: scope1count=1 scope1_0_kind=Board scope1_0_value=Board scope2count=1 scope2_0_kind=Board scope2_0_value=Board commentlength=0 cornerstyle=45-Degree minsetback=100 maxsetback=100
RoutingLayers [All] p0: scope1count=1 scope1_0_kind=Board scope1_0_value=Board scope2count=1 scope2_0_kind=Board scope2_0_value=Board commentlength=0 top layer=Automatic mid layer 1=Automatic mid layer 2=Automatic mid layer 3=Automatic mid layer 4=Automatic mid layer 5=Automatic mid layer 6=Automatic bottom layer=Automatic
RoutingPriority [All] p0: scope1count=1 scope1_0_kind=Board scope1_0_value=Board scope2count=1 scope2_0_kind=Board scope2_0_value=Board commentlength=0
RoutingTopology [All] p0: scope1count=1 scope1_0_kind=Board scope1_0_value=Board scope2count=1 scope2_0_kind=Board scope2_0_value=Board commentlength=0 topology=Shortest
RoutingVias [All] p0: scope1count=1 scope1_0_kind=Board scope1_0_value=Board scope2count=1 scope2_0_kind=Board scope2_0_value=Board commentlength=0 holewidth=8 width=34 viastyle="Through Hole" minholewidth=7.87 minwidth=16 maxholewidth=40 maxwidth=65
RoutingVias ThermalPadVias [All] p0 off: scope1count=1 scope1_0_kind=Board scope1_0_value=Board scope2count=1 scope2_0_kind=Board scope2_0_value=Board commentlength=63 holewidth=7.87 width=19.68 viastyle="Through Hole" minholewidth=7.87 minwidth=19.68 maxholewidth=12.99 maxwidth=23.62 // Protel DXP Scope 1 Expression Was: IsVia and InAnyComponent
RoutingVias ThermalPadVias [IsVia and InAnyComponent] p1: holewidth=7.87 width=19.68 viastyle="Through Hole" minholewidth=7.87 minwidth=19.68 maxholewidth=12.99 maxwidth=23.62
RoutingVias [All] p2: holewidth=8 width=34 viastyle="Through Hole" minholewidth=7.87 minwidth=16 maxholewidth=40 maxwidth=65
ShortCircuit [All] p0: scope1count=1 scope1_0_kind=Board scope1_0_value=Board scope2count=1 scope2_0_kind=Board scope2_0_value=Board commentlength=0 allowed=FALSE
SilkToBoardRegionClearance [All] p0 off: scope1count=1 scope1_0_kind=Board scope1_0_value=Board scope2count=1 scope2_0_kind=Board scope2_0_value=Board commentlength=130 // Protel DXP Scope 1 Expression Was: Not ((IsComment or IsDesignator) And (Hide <> 'False')) and not InRegion(1000,500,4000,800)
SilkToBoardRegionClearance [Not ((IsComment or IsDesignator) And (Hide <> 'False')) and not InRegion(1000,500,4000,800)] p1:
SilkToSilkClearance [All] p0: scope1count=1 scope1_0_kind=Board scope1_0_value=Board scope2count=1 scope2_0_kind=Board scope2_0_value=Board commentlength=0
SilkToSilkClearance SilkToSilkClearance_Pb-FreeLogo [All] p0 off: scope1count=1 scope1_0_kind=Board scope1_0_value=Board scope2count=1 scope2_0_kind=Board scope2_0_value=Board commentlength=120 // Protel DXP Scope 2 Expression Was: (HasFootprint('Pb-Free_Overlay_Medium') OR HasFootprint('Pb-Free_Overlay_Small'))
SilkToSilkClearance SilkToSilkClearance_Pb-FreeLogo [(HasFootprint('Pb-Free_Overlay_Medium') OR HasFootprint('Pb-Free_Overlay_Small')) vs (HasFootprint('Pb-Free_Overlay_Medium') OR HasFootprint('Pb-Free_Overlay_Small'))] p1: silktosilkclearance=0
SilkToSilkClearance [All] p2: silktosilkclearance=3.94
SilkToSolderMaskClearance "Silk to Solder Mask Opening" [All] p0: scope1count=1 scope1_0_kind=Board scope1_0_value=Board scope2count=1 scope2_0_kind=Board scope2_0_value=Board commentlength=0
SilkToSolderMaskClearance SilkToComponentPadClearance [All] p0 off: scope1count=1 scope1_0_kind=Board scope1_0_value=Board scope2count=1 scope2_0_kind=Board scope2_0_value=Board commentlength=87 // Protel DXP Scope 1 Expression Was: (IsPad or IsFill or IsRegion) and InAnycomponent
SilkToSolderMaskClearance SilkToComponentPadClearance [(IsPad or IsFill or IsRegion) and InAnycomponent] p1: minsilkscreentomaskgap=3 clearancetoexposedcopper=TRUE
SilkToSolderMaskClearance "Silk to Solder Mask Opening" [All] p2: minsilkscreentomaskgap=3.94 clearancetoexposedcopper=FALSE
SolderMaskExpansion SolderMaskExpansion_NPTH [All] p0 off: scope1count=1 scope1_0_kind=Board scope1_0_value=Board scope2count=1 scope2_0_kind=Board scope2_0_value=Board commentlength=76 expansion=5 // Protel DXP Scope 1 Expression Was: IsThruPin And (PadIsPlated = 'False')
SolderMaskExpansion SolderMaskExpansion_PTH [All] p0 off: scope1count=1 scope1_0_kind=Board scope1_0_value=Board scope2count=1 scope2_0_kind=Board scope2_0_value=Board commentlength=48 expansion=2.5 // Protel DXP Scope 1 Expression Was: IsThruPin
SolderMaskExpansion [All] p0: scope1count=1 scope1_0_kind=Board scope1_0_value=Board scope2count=1 scope2_0_kind=Board scope2_0_value=Board commentlength=0 expansion=0
SolderMaskExpansion SolderMaskExpansion_NPTH [IsThruPin And (PadIsPlated = 'False')] p1: expansion=5 istentingtop=FALSE soldermaskfromhole=TRUE
SolderMaskExpansion SolderMaskExpansion_PTH [IsThruPin] p2: expansion=2.5 istentingtop=FALSE
SolderMaskExpansion [All] p3: expansion=0 istentingtop=FALSE
UnRoutedNet [All] p0: scope1count=1 scope1_0_kind=Board scope1_0_value=Board scope2count=1 scope2_0_kind=Board scope2_0_value=Board commentlength=0
UnRoutedNet [All] p1: checkbadconnections=TRUE
UnpouredPolygon [All] p0: scope1count=1 scope1_0_kind=Board scope1_0_value=Board scope2count=1 scope2_0_kind=Board scope2_0_value=Board commentlength=0
Width Width_50OHM [All] p0: scope1count=1 scope1_0_kind=NetClass scope1_0_value="50 OHM" scope2count=1 scope2_0_kind=Board scope2_0_value=Board commentlength=0 maxlimit=6.5 minlimit=5 preferedwidth=6.5
Width [All] p0: scope1count=1 scope1_0_kind=Board scope1_0_value=Board scope2count=1 scope2_0_kind=Board scope2_0_value=Board commentlength=0 maxlimit=100 minlimit=5 preferedwidth=15
Width Width_50OHM [InNetClass('50 OHM')] p1: maxlimit=6.5 minlimit=5 preferedwidth=6.5
Width [All] p2: maxlimit=100 minlimit=5 preferedwidth=15 checkconnectedcopper=TRUE
14 further rules are at their usual default settings.

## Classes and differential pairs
net class Voltage: 1V2_OB NetL3_1
net class POWER: 1V2_OB NetL3_1
component class Header: J3 J4 J5 J6 J10 J16
component class DLP096B_System_Power: C1 C2 C3 C4 C5 C6 C7 C8 C9 C10 C11 C12 C13 C14 C15 C16 C26 C501 C503 C506 D2 D500 J1 J3 J4 J5 J6 J7 J8 L1 L2 L3 L5 R1 R2 R3 R4 R5 R6 R7 R8 R9 R10 R15 R22 R24 R27 R28 R36 R500 TP1 TP4 TP5 TP6 TP7 TP17 U1 U2 U3 U4 U6 U8 U10 U11
component class DLP096B_SoC_Power_Clock: C30 C31 C32 C43 C44 C45 C46 C47 C48 C54 C508 C509 C510 C511 C512 C513 C514 C515 C516 C517 C518 C519 C520 C521 C522 C523 C524 C525 C527 C528 C529 C530 C531 C532 C535 C536 C537 C538 C539 C540 C541 C542 C543 C545 C546 C547 C548 C549 C550 C551 C552 C553 C554 FB2 R62 R73 R74 R519 TP22 TP23 U12 Y1
component class DLP096B_SoC_Memory: C35 C36 C38 C51 C526 C533 C534 C544 C555 C556 C557 J10 R16 R18 R23 R25 R26 R29 R46 R47 R48 R63 R64 R67 R68 R70 R71 R505 R520 U7 U15 U17 U18
component class DLP096B_LED_Driver: C17 C18 C19 C20 C21 C22 C23 C65 C66 C68 C70 D1 D3 D9 D10 D501 J2 J16 L4 Q1 Q4 R11 R12 R13 R14 R30 R49 R50 R51 R76 R78 R79 R80 R81 TP2 TP3 TP14 TP15 TP16 U5 U20
component class DLP096B_Interfaces_Sockets: D5 D6 J11 J12 J13 J14 J15 R31 R32 R75
component class DLP096B_DMD_Power: C24 C25 C27 C28 C29 C33 C34 C37 C39 C40 C69 C504 C505 C507 D4 D7 D8 L6 Q2 Q3 R17 R19 R20 R21 R33 R37 R38 R39 R40 R41 R42 R77 R503 R504 TP8 TP9 TP10 TP11 TP12 U9 U14 U22
component class DLP096B_DMD_Interface: C41 C42 C49 C50 C52 C53 C55 C56 C57 C58 C59 C60 C61 C62 C63 C64 C71 C72 J9 R34 R35 R43 R44 R45 R65 R66 R69 R72 R82 R83 R84 R85 R86 R532 TP13 TP18 TP19 TP20 TP21 U13 U16 U19 U21
component class "Mounting Holes": H1 H2 H3 H4
component class Logo: Logo2
component class DLP096B_Hardware: FID1 FID2 FID3 FID4 FID5 FID6 H1 H2 H3 H4 H500 H501 H502 H503 LBL1 Logo1 Logo2 Logo3 Logo4 SH-J1 SH-J2 SH-J3 SH-J4 SH-J5 SH-J6 SH-J7 SH-J8 ZZ1 ZZ2 ZZ3 ZZ4 ZZ5
component class FiducialMark: FID1 FID2 FID3 FID4 FID5 FID6
component class AssemblyNote: ZZ1 ZZ2 ZZ3 ZZ4 ZZ5
component class Label: LBL1

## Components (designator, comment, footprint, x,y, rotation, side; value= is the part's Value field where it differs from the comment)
C1 "GCM188L81H104KA57D" FP-GCM188L81H104KA57D_0603-MFG 720.31,2836.22 r180 top locked
C2 "06035A560FAT2A" 0603 964.68,2591.79 r180 top locked
C3 "GRM1885C1H122JA01D" 0603 997.4,2467.8 r90 top locked
C4 "GCJ32DL8EL225KA07L" FP-GCJ32DL8EL225KA07L_1210-MFG 653.54,2246.52 r90 top locked
C5 "GCJ32DL8EL225KA07L" FP-GCJ32DL8EL225KA07L_1210-MFG 796.05,2246.52 r90 top locked
C6 "GCM155R71H391KA37D" 0402 1744.21,2297.32 r180 top locked
C7 "C0402C104K8RACTU" 0402 1883.02,2297.27 r0 top locked
C8 "CGA2B2C0G1H151J050BA" 0402 2488.55,2297.27 r180 top locked
C9 "C0402C104K8RACTU" 0402 2616.86,2297.27 r0 top locked
C10 "GRM155R60J475ME47J" 0402 3166.6,2264.16 r270 top locked
C11 "GRM186R60J226ME15D" 0603 2843.88,2276.16 r0 top locked
C12 "GRM186R60J226ME15D" 0603 3396.16,2223.7 r90 top locked
C13 "CC0805ZKY5V6BB106" 0805_HV 2616.86,2217.29 r0 top locked
C14 "CC0805ZKY5V6BB106" 0805_HV 1883.02,2217.29 r0 top locked
C15 "UCL1A331MNL1GS" CL_800x1000 1103.6,1983.5 r270 top
C16 "UUD1A221MCL1GS" SM_RADIAL_6.3BMM 2159.24,2349.07 r0 top
C17 "GRM033R61A104KE84D" 0201_033#1 4020.99,1898.95 r90 top locked
C18 "CGA3E1X7R1C105K080AC" 0603 4033.36,1788.02 r270 top locked
C19 "C1608X5R1V475K080AC" 0603 3681.26,1749.17 r0 top locked
C20 "GRT155R71A474KE01D" 0402L 3401.06,1637.65 r0 top
C21 "C1608C0G2A471J" 0603 3919.75,1682.72 r0 top locked
C22 "C1608X5R1V475K080AC" 0603 3681.26,1678.72 r0 top locked
C23 "C1608X5R1V475K080AC" 0603 3681.26,1608.27 r0 top locked
C24 "CGA4J1X7R1E475K125AC" 0805L 4578.59,1569.44 r0 top locked
C25 "GCM188R71E104KA57D" 0603L 4115.92,1517.21 r90 top locked
C26 "C0402C104K8RACTU" 0402 1768.18,1464.17 r180 top locked
C27 "GCM188R71E104KA57D" 0603L 3989.06,1437.45 r180 top locked
C28 "GCM188R71E104KA57D" 0603L 3785.37,1431.09 r0 top locked
C29 "GCM1555C1H4R7CA16D" 0402 4574.23,1413.83 r0 top locked
C30 "C1608X5R1E335K080AC" 0603 2612.64,1361.99 r90 top locked
C31 "C1608X5R1E335K080AC" 0603 2682.04,1361.99 r90 top locked
C32 "C1608X5R1E335K080AC" 0603 2751.51,1361.99 r90 top locked
C33 "GCM188R71E104KA57D" 0603L 3989.06,1375.08 r180 top locked
C34 "GCM188R71E105KA64D" 0603L 3989.06,1306.09 r0 top locked
C35 "GRM033R61A104KE84D" 0201_033#2 2153.06,1256.14 r0 top locked
C36 "GRM033R61A104KE84D" 0201_033#1 2153.06,1214.65 r0 top locked
C37 "GCM188R71E105KA64D" 0603L 3989.06,1252.85 r180 top locked
C38 "C1608X5R1V475K080AC" 0603 2171.57,1307.14 r0 top locked
C39 "CGA5L1X7S1A226M160AC" 1206_190L 4439.89,1157.74 r90 top locked
C40 "CGA2B2X7R1H222K050BA" 0402L 3921.89,1203.72 r0 top locked
C41 "GCM155L81E104KE02D" 0402 3419.86,1129.49 r0 top locked
C42 "GCM155L81E104KE02D" 0402 3528.59,1129.49 r180 top locked
C43 "C1608X5R1E335K080AC" 0603 2225.45,1110.68 r180 top locked
C44 "C1608X5R1E335K080AC" 0603 2225.45,1031.22 r180 top locked
C45 "C1608X5R1E335K080AC" 0603 2225.44,951.75 r180 top locked
C46 "C1608X5R1E335K080AC" 0603 2233.2,835.83 r180 top locked
C47 "C1608X5R1E335K080AC" 0603 2110.99,767.4 r90 top locked
C48 "GRM033R61A104KE84D" 0201_033#1 2167.41,768.01 r90 top locked
C49 "GCM155L81E104KE02D" 0402 3419.86,714.84 r0 top locked
C50 "GCM155L81E104KE02D" 0402 3528.59,714.84 r180 top locked
C51 "GRM186R60J226ME15D" 0603 557.38,638.09 r180 top locked
C52 "GRM188R71A225KE15J" 0603L 4217.51,575.03 r90 top locked
C53 "GRM188R71A225KE15J" 0603L 4217.51,458.58 r270 top locked
C54 "C1608X5R1V475K080AC" 0603 2273.16,439.22 r180 top locked
C55 "GCM155R71A104KA55D" 0402L 3767.94,418.38 r270 top locked
C56 "GCM155L81E104KE02D" 0402 3555.92,301.28 r0 top locked
C57 "GCM155L81E104KE02D" 0402 3555.92,246.28 r180 top locked
C58 "GRM188R71A225KE15J" 0603L 4243.3,163.04 r0 top locked
C59 "GCM188R71E104KA57D" 0603L 3734.48,162.48 r180 top locked
C60 "GCM155R71A104KA55D" 0402L 4231.49,103.18 r0 top locked
C61 "GCM155R71A104KA55D" 0402L 3746.29,101.36 r180 top locked
C62 "GCM155R71A104KA55D" 0402L 3746.29,55.38 r180 top locked
C63 "GCM188R71E104KA57D" 0603L 4243.3,44.37 r0 top locked
C64 "GCM188R71E104KA57D" 0603L 3734.48,-1.74 r180 top locked
C65 "C0402C104K8RACTU" 0402L 3492.43,1625.2 r180 top
C66 "GRT155R71A474KE01D" 0402L 3326.3,1612.63 r90 top
C68 "GRT155R71A474KE01D" 0402L 3326.3,1526.75 r270 top
C69 "C0402C104K8RACTU" 0402 1855.03,1912.3 r180 top
C70 "GCM188R71E104KA57D" 0603L 3959.09,2384.61 r180 top
C71 "GCM155L81E104KE02D" 0402 4507.54,533.99 r0 top
C72 "GRM1555C1H121FA01D" 0402 4367.32,435.17 r270 top
C501 "C0402C104K8RACTU" 0402 1846.89,1641.21 r180 bottom locked
C503 "C0402C104K8RACTU" 0402 1462.92,1410.39 r90 bottom locked
C504 "GCM188R71E105KA64D" 0603L 3878.72,1353.58 r90 bottom locked
C505 "CGA3E3X7R1H224K080AB" 0603L 3989.06,1281.53 r180 bottom locked
C506 "C0402C104K8RACTU" 0402 1490.93,1235.97 r90 bottom locked
C507 "C0402C104K8RACTU" 0402 4145.06,1085.17 r180 bottom locked
C508 "GRM033R61A104KE84D" 0201_033#1 2858.14,1074.92 r0 bottom
C509 "GRM033R61A104KE84D" 0201_033#1 2773.3,1052.42 r180 bottom locked
C510 "GRM033R61A104KE84D" 0201_033#1 2691.81,1036.67 r270 bottom locked
C511 "GRM033R61A104KE84D" 0201_033#1 2660.31,1036.67 r270 bottom locked
C512 "GRM033R61A104KE84D" 0201_033#1 2628.82,1036.67 r270 bottom locked
C513 "C1608X5R1E335K080AC" 0603 2225.44,1031.22 r180 bottom locked
C514 "GRM033R61A104KE84D" 0201_033#1 2928.03,1020.92 r180 bottom locked
C515 "GRM033R61A104KE84D" 0201_033#1 2833.54,1020.92 r0 bottom locked
C516 "GRM033R61A104KE84D" 0201_033#1 2833.54,989.43 r0 bottom locked
C517 "GRM033R61A104KE84D" 0201_033#1 2912.28,973.68 r90 bottom locked
C518 "GRM033R61A104KE84D" 0201_033#1 2723.3,973.68 r270 bottom locked
C519 "GRM033R61A104KE84D" 0201_033#1 2597.32,973.68 r90 bottom locked
C520 "GRM033R61A104KE84D" 0201_033#1 2760.38,972.52 r270 bottom locked
C521 "C1608X5R1E335K080AC" 0603 2225.44,951.75 r180 bottom locked
C522 "GRM033R61A104KE84D" 0201_033#1 2865.04,957.93 r180 bottom locked
C523 "GRM033R61A104KE84D" 0201_033#1 2628.82,942.18 r270 bottom locked
C524 "GRM033R61A104KE84D" 0201_033#1 2565.82,939.43 r90 bottom locked
C525 "GRM033R61A104KE84D" 0201_033#1 2534.33,939.43 r90 bottom locked
C526 "CGA3E1X7R1C105K080AC" 0603 1548.2,898.21 r0 bottom locked
C527 "GRM033R61A104KE84D" 0201_033#1 2896.53,894.94 r180 bottom locked
C528 "GRM033R61A104KE84D" 0201_033#1 2628.82,863.44 r90 bottom locked
C529 "GRM033R61A104KE84D" 0201_033#1 2597.1,863.44 r90 bottom locked
C530 "GRM033R61A104KE84D" 0201_033#2 2990.77,863.44 r0 bottom locked
C531 "GRM033R61A104KE84D" 0201_033#1 2930.79,863.44 r180 bottom locked
C532 "GRM033R61A104KE84D" 0201_033#1 2865.04,831.95 r180 bottom locked
C533 "GRM033R61A104KE84D" 0201_033#2 1609.49,795.59 r270 bottom locked
C534 "GRM033R61A104KE84D" 0201_033#2 1454.77,795.59 r270 bottom locked
C535 "GRM033R61A104KE84D" 0201_033#1 2928.09,802.45 r180 bottom locked
C536 "GRM033R61A104KE84D" 0201_033#1 2581.52,800.45 r0 bottom locked
C537 "GRM033R61A104KE84D" 0201_033#1 2943.78,753.21 r90 bottom locked
C538 "GRM033R61A104KE84D" 0201_033#1 2912.28,753.21 r90 bottom locked
C539 "GRM033R61A104KE84D" 0201_033#1 2880.79,753.21 r90 bottom locked
C540 "GRM033R61A104KE84D" 0201_033#1 2628.82,753.21 r90 bottom locked
C541 "GRM033R61A104KE84D" 0201_033#1 2597.32,753.21 r90 bottom locked
C542 "GRM033R61A104KE84D" 0201_033#1 2707.5,737.46 r180 bottom locked
C543 "GRM033R61A104KE84D" 0201_033#1 2817.79,720.91 r90 bottom locked
C544 "C1608X5R1V475K080AC" 0603 1549.31,699.84 r180 bottom locked
C545 "GRM033R61A104KE84D" 0201_033#2 2531.55,711.16 r180 bottom locked
C546 "GRM033R61A104KE84D" 0201_033#1 2644.56,705.96 r180 bottom locked
C547 "GRM033R61A104KE84D" 0201_033#1 2729.62,690.21 r90 bottom locked
C548 "GRM033R61A104KE84D" 0201_033#1 2691.81,690.21 r90 bottom locked
C549 "GRM033R61A104KE84D" 0201_033#1 2786.3,688.25 r90 bottom locked
C550 "GRM033R61A104KE84D" 0201_033#1 2930.79,674.47 r180 bottom locked
C551 "GRM033R61A104KE84D" 0201_033#1 2833.84,674.47 r0 bottom locked
C552 "GRM033R61A104KE84D" 0201_033#1 2613.07,674.47 r180 bottom locked
C553 "GRM033R61A104KE84D" 0201_033#1 2550.08,674.47 r180 bottom locked
C554 "C1608X5R1E335K080AC" 0603 2459.34,622.93 r180 bottom locked
C555 "C0402C104K8RACTU" 0402 608.54,506.88 r90 bottom locked
C556 "C0402C104K8RACTU" 0402 518.85,255.67 r180 bottom
C557 "C0402C104K8RACTU" 0402 664.56,255.67 r180 bottom
D1 "B0530WSQ-13-F" SOD-323#1 4554.96,2377.62 r270 top
D2 "LSL29K-G1H2-1-Z" FP-LSL29K-G1H2-1-Z_0603-0 533.34,2181.78 r90 top locked
D3 "ZHCS2000TA" SOT-26 3944.95,2035.68 r270 top locked
D4 "SL02-M-18" DO-219AB 4439.89,1337.58 r270 top locked
D5 "LSL29K-G1H2-1-Z" FP-LSL29K-G1H2-1-Z_0603-0 2833.82,1341.6 r270 top locked
D6 "LSL29K-G1H2-1-Z" FP-LSL29K-G1H2-1-Z_0603-0 2911.38,1341.6 r270 top locked
D7 "BAT54XYH" FP-BAT54XYH_SOT363-IPC_C 3792.32,1351.61 r180 top locked
D8 "SZMM3Z3V3ST1G" SOD-323#2 4328.3,1046.98 r0 top locked
D9 "B0530WSQ-13-F" SOD-323#1 4483.21,2334.41 r270 top
D10 "B0530WSQ-13-F" SOD-323#1 4412.25,2289.61 r270 top
D500 "B540CQ-13-F" SMC 525.5,2627.29 r270 bottom locked
D501 "B0530WSQ-13-F" SOD-323#1 4110.9,1830.09 r270 bottom locked
FB2 "BLM18EG121SN1D" FP-BLM18EG121SN1D_0603-MFG 2278.08,513.33 r180 top locked
FID1 "Fiducial" Fiducial10-20#1 4235.33,2722.07 r0 top locked
FID2 "Fiducial" Fiducial10-20#1 280.77,0 r0 top locked
FID3 "Fiducial" Fiducial10-20#2 280.79,2856.95 r0 top locked
FID4 "Fiducial" Fiducial10-20#2 280.79,2856.95 r180 bottom locked
FID5 "Fiducial" Fiducial10-20#1 280.77,0 r180 bottom locked
FID6 "Fiducial" Fiducial10-20#1 4235.33,2722.07 r180 bottom locked
H1 "NY PMS 440 0025 PH" "NY PMS 440 0025 PH" 0,2737.45 r0 top locked
H2 "NY PMS 440 0025 PH" "NY PMS 440 0025 PH" 4528,2737.45 r0 top locked
H3 "NY PMS 440 0025 PH" "NY PMS 440 0025 PH" 0,0 r0 top locked
H4 "NY PMS 440 0025 PH" "NY PMS 440 0025 PH" 4528,0 r0 top locked
H500 "1902C" Keystone_1902C 4528,2737.45 r180 bottom locked
H501 "1902C" Keystone_1902C 0,2737.45 r180 bottom locked
H502 "1902C" Keystone_1902C 4528,0 r180 bottom locked
H503 "1902C" Keystone_1902C 0,0 r180 bottom locked
J1 "EJ508A" Memory_EJ508A 221.88,2236.18 r270 top
J2 "2005280060" FP-2005280060_CONN_11MM2_5MM25-MFG 4552.12,2259.36 r270 bottom
J3 "22284033" Molex_0022284033 2751.54,1984.78 r180 top locked
J4 "22284033" Molex_0022284033 3296.54,1984.78 r180 top locked
J5 "22284033" Molex_0022284033 2156.54,1978.66 r0 top locked
J6 "22284033" Molex_0022284033 1611.54,1978.66 r0 top locked
J7 "571-0500" 571-0500 182.7,1723.5 r0 top locked
J8 "571-0100" 571-0100 182.7,973.5 r0 top locked
J9 "DMD Interposer" FP-2516672_SMD_CONN_LGA-56-MFG 3988.89,308.14 r90 top locked
J10 "TSM-104-01-L-DV" Samtec_TSM-104-01-x-DV 143.27,410.2 r180 top locked
J11 "702461002" FP-702461002_HDR10-MFG 1413.4,1.24 r180 top
J12 "FTR-110-03-G-D-06" FP-FTR-110-03-G-D-06_HDR19-MFG 640.94,-0.09 r0 top locked
J13 "RSM-110-02-L-D" Samtec_RSM-110-02-x-D 3307.19,-0.09 r180 top locked
J14 "FLE-108-01-G-DV-A" Samtec_FLE-108-01-x-DV-A 2106.28,-0.09 r180 top locked
J15 "FLE-108-01-G-DV-A" Samtec_FLE-108-01-x-DV-A 2689.59,-0.09 r180 top locked
J16 "TSW-104-07-G-S" TSW-104-07-G-S 4646.25,2257.62 r270 top
L1 "MSS1210-153ME" MSS1210 1304.76,2584.22 r270 top locked
L2 "XAL5030-222MEB" XAL5030 1860.38,2612.48 r0 top
L3 "XAL5030-222MEB" XAL5030 2812.21,2463.89 r270 top locked
L4 "SRN5040TA-220M" SRN5040TA 4030.55,2247.8 r90 top locked
L5 "MLP2012V2R2MT0S1" 0805_HV 3309.74,2230.94 r270 top locked
L6 "FDSD0420D-4R7M" FDSD0420 4597.78,1245.02 r90 top locked
LBL1 "THT-14-423-10" Label_650x200 3524.72,2481.66 r0 top
Logo1 "FCC disclaimer" FCC_disclaimer 3087.81,2840.05 r0 top locked
Logo2 "Texas Instruments" TI_Stacked_Overlay_Small 3221,2717.56 r0 top
Logo3 "WEEE logo" WEEE_Minimum 938.51,935.59 r0 top locked
Logo4 "CE Mark" CE_Mark_5mm 940.47,460.2 r0 top locked
Q1 "DMT3020LFDB-13" U-DFN2020-6_B 4306.7,2423.91 r0 top
Q2 "NX3008NBKS,115" FP-NX3008NBKS,115_TSSOP6-IPC_C 4339.62,946.48 r180 top locked
Q3 "NX3008CBKS,115" SOT-363 4500.66,920.89 r180 top locked
Q4 "DMT3020LFDB-13" U-DFN2020-6_B 4307.78,2257.18 r0 top
R1 "CRCW0603158KFKEA" 0603 997.4,2715.77 r270 top locked
R2 "CRCW0603100KFKEA" 0603 923.09,2467.8 r270 top locked
R3 "CR0603-FX-3163ELF" FP-CR0603-FX-3163ELF_0603-MFG 965.9,2355.36 r0 top locked
R4 "CRCW04021K80JNED" 0402L 534.88,2291.76 r90 top locked
R5 "ERJ-6ENF1003V" 0805_HV 2018.69,2575.74 r270 top
R6 "RC0603FR-07180KL" 0603 2095.46,2711.22 r270 top
R7 "RC0603FR-0775KL" 0603 2843.88,2184.26 r180 top locked
R8 "RC0603FR-07150KL" 0603 2992.09,2184.26 r180 top locked
R9 "RC0603FR-07562KL" 0603 2095.46,2561.62 r270 top
R10 "ERJ-6ENF1003V" 0805_HV 2616.86,2112.99 r180 top locked
R11 "MCR25JZHFLR110" 1210 3649.76,1888.94 r270 top locked
R12 "RC0603FR-078K2L" 0603 3919.75,1747.63 r180 top locked
R13 "CRCW04021K80JNED" 0402L 3401.06,1679.17 r180 top
R14 "CRCW04023K00JNED" 0402L 3401.06,1720.69 r180 top
R15 "ERJ-8ENF3481V" 1206 1504.74,1583.01 r180 top locked
R16 "MCR01MZPJ000" 0402 2030.72,1517.32 r270 top locked
R17 "ERA-2AEB822X" FP-ERA-2AEB822X_0402-IPC_C 4340.33,1515.27 r270 top locked
R18 "RC0201JR-0710KL" 0201#1 2085.41,1506.97 r270 top locked
R19 "ERA-2AEB104X" FP-ERA-2AEB104X_0402-IPC_C 4262.27,1500.46 r180 top locked
R20 "ERA-2AEB104X" FP-ERA-2AEB104X_0402-IPC_C 4565.36,1482.23 r180 top locked
R21 "TNPW040215K6BEED" FP-TNPW040215K6BEED_0402-IPC_C 4646.06,1482.23 r180 top locked
R22 "ERJ-6ENF1003V" 0805_HV 1585.77,1434.9 r270 top locked
R23 "RC0201JR-0710KL" 0201#1 2519.82,1493.21 r0 top locked
R24 "CRCW080510K2FKEA" 0805_HV 1360.62,1428.49 r270 top locked
R25 "RC0201JR-0710KL" 0201#1 2078.92,1418.98 r270 top locked
R26 "RC0201JR-0710KL" 0201#1 2519.82,1393.21 r0 top locked
R27 "CRCW080510K2FKEA" 0805_HV 1383.27,1237.49 r270 top locked
R28 "ERJ-6ENF1003V" 0805_HV 1585.77,1226.64 r270 top locked
R29 "RC0201JR-0710KL" 0201#1 2631.07,1248.38 r90 top locked
R30 "CRCW04023K00JNED" 0402L 3240.8,1613.07 r270 top
R31 "CRCW04021K80JNED" 0402L 2833.82,1236.74 r270 top locked
R32 "CRCW04021K80JNED" 0402L 2911.38,1236.74 r270 top locked
R33 "CRCW040233K2FKED" 0402 4024.88,1203.72 r0 top locked
R34 "CRCW060310K0JNEA" 0603 3319.63,1137.51 r270 top locked
R35 "CRCW060310K0JNEA" 0603 3617.77,1137.51 r270 top locked
R36 "RC0603FR-074K32L" 0603 1351.77,1115.55 r180 top locked
R37 "ERJ-2GEJ102X" 0402L 4141.12,1085.17 r180 top locked
R38 "CRCW040213R0JNED" 0402L 4416.95,991.75 r90 top locked
R39 "ERJ-2GEJ102X" 0402L 4227.71,926.79 r90 top locked
R40 "ERJ-2GEJ103X" 0402L 4599.09,946.48 r180 top locked
R41 "CRCW040239R0JNED" 0402L 4599.09,895.3 r180 top locked
R42 "CRCW040239R0JNED" 0402L 4328.73,860.32 r0 top locked
R43 "CRCW060310K0JNEA" 0603 3413.6,820.04 r180 top locked
R44 "CRCW060310K0JNEA" 0603 3319.63,720.01 r270 top locked
R45 "CRCW060310K0JNEA" 0603 3617.77,720.01 r270 top locked
R46 "ERJ-3EKF49R9V" 0603 716.35,638.09 r0 top locked
R47 "RC0201JR-0710KL" 0201#1 365.13,560.2 r0 top locked
R48 "ERJ-2GEJ102X" 0402L -82.21,560.2 r0 top locked
R49 "CRCW04021K80JNED" 0402L 3283.55,1612.6 r270 top
R50 "CRCW04023K00JNED" 0402L 3240.8,1526.57 r90 top
R51 "CRCW04021K80JNED" 0402L 3283.55,1526.76 r90 top
R62 "CRCW04022K32FKED" 0402 2386.96,441.29 r90 top locked
R63 "RC0201JR-0710KL" 0201#1 365.13,460.2 r0 top locked
R64 "ERJ-2GEJ102X" 0402L -82.21,460.2 r0 top locked
R65 "RC0201JR-0710KL" 0201#1 3729.21,418.38 r90 top locked
R66 "CRCW060310K0JNEA" 0603 3408.6,402.55 r180 top locked
R67 "RC0201JR-0710KL" 0201#1 365.13,360.2 r0 top locked
R68 "ERJ-2GEJ102X" 0402L -82.21,360.98 r0 top locked
R69 "CRCW060310K0JNEA" 0603 3321.32,307.91 r0 top locked
R70 "RC0201JR-0710KL" 0201#1 365.13,260.2 r0 top locked
R71 "ERJ-2GEJ102X" 0402L -82.21,259.03 r0 top locked
R72 "CRCW060310K0JNEA" 0603 3321.32,239.44 r0 top locked
R73 "CRCW040210K0FKED" 0402 728.24,575.8 r180 top
R74 "RMCF0805ZT0R00" FP-RMCF0805ZT0R00_0805-IPC_C 2242.29,754.57 r0 top
R75 "ERJ-2GEJ101X" 0402L 355.48,132.96 r270 top
R76 "MCR01MZPJ000" 0402 3815.8,1672.98 r270 top
R77 "ERJ-2GEJ103X" 0402L 1947.17,1911 r0 top
R78 "ERJ-2GEJ101X" 0402L 4143.06,2020.99 r90 top
R79 "ERJ-2GEJ101X" 0402L 4192.79,2020.43 r90 top
R80 "ERJ-2GEJ101X" 0402L 4292.24,2020.01 r90 top
R81 "ERJ-2GEJ101X" 0402L 4242.51,2020.43 r90 top
R82 "RC0201JR-0710KL" 0201#2 4218.3,690.49 r90 top
R83 "RC0603FR-0756RL" 0603 4326.16,521.14 r180 top
R84 "RC0603FR-0756RL" 0603 4308.7,423.51 r270 top
R85 "RC0201JR-0710KL" 0201#2 4624.63,539.81 r90 top
R86 "RC0201JR-0710KL" 0201#2 4588.16,539.69 r90 top
R500 "CRCW040241K2FKED" 0402 844.28,2532.12 r270 bottom locked
R503 "ERA-2AEB1212X" FP-ERA-2AEB1212X_0402-IPC_C 4115.92,1240.09 r270 bottom locked
R504 "ERA-2AEB104X" FP-ERA-2AEB104X_0402-IPC_C 4069.89,1164.01 r270 bottom locked
R505 "RC0201JR-0710KL" 0201#3 1511.83,601.17 r90 bottom locked
R519 "CRCW040210K0FKED" 0402 2386.96,441.29 r270 bottom locked
R520 "MCR01MZPJ000" 0402 1507.89,434.77 r0 bottom locked
R532 "CRCW060310K0JNEA" 0603 3486.11,379.12 r180 bottom locked
SH-J1 "M7582-05" Harwin_M7582-05 2801.54,1984.78 r0 top locked
SH-J2 "M7582-05" Harwin_M7582-05 3346.54,1984.78 r0 top locked
SH-J3 "M7582-05" Harwin_M7582-05 2106.54,1978.66 r0 top locked
SH-J4 "M7582-05" Harwin_M7582-05 1561.54,1978.66 r0 top locked
SH-J5 "M7582-05" Harwin_M7582-05 143.27,260.19 r0 top locked
SH-J6 "M7582-05" Harwin_M7582-05 143.27,460.2 r0 top locked
SH-J7 "M7582-05" Harwin_M7582-05 143.27,560.2 r0 top locked
SH-J8 "M7582-05" Harwin_M7582-05 143.27,360.2 r0 top locked
TP1 "5001" Keystone5001 329.46,2634 r90 top locked
TP2 "TP_H0.45P0.75" TP_H045P075 4143.43,2089.2 r90 top
TP3 "TP_H0.45P0.75" TP_H045P075 4197.91,2089.2 r90 top
TP4 "5001" Keystone5001 1611.54,2196.14 r90 top locked
TP5 "5001" Keystone5001 2424.51,2112.99 r90 top locked
TP6 "5001" Keystone5001 2751.54,1781.7 r90 top locked
TP7 "5001" Keystone5001 3297.24,1781.7 r90 top locked
TP8 "5001" Keystone5001 4247.21,1690.54 r90 top
TP9 "5001" Keystone5001 4548.08,1690.54 r270 top locked
TP10 "5001" Keystone5001 3644.55,1399.54 r90 top
TP11 "5001" Keystone5001 3908.42,983.88 r270 top locked
TP12 "5001" Keystone5001 4501.69,704.62 r180 top locked
TP13 "TP_H0.45P0.75" TP_H045P075 4281.77,264.5 r180 top
TP14 "TP_H0.45P0.75" TP_H045P075 4306.86,2087.97 r0 top
TP15 "TP_H0.45P0.75" TP_H045P075 4252.38,2087.15 r0 top
TP16 "TP_H0.45P0.75" TP_H045P075 3801.12,1750.42 r0 top
TP17 "5001" Keystone5001 913.66,1332.98 r90 top
TP18 "TP_H0.45P0.75" TP_H045P075 4389.08,184.84 r90 top
TP19 "TP_H0.45P0.75" TP_H045P075 4389.08,277.09 r90 top
TP20 "TP_H0.45P0.75" TP_H045P075 4389.08,323.21 r90 top
TP21 "TP_H0.45P0.75" TP_H045P075 4389.08,230.96 r90 top
TP22 "TP_H0.45P0.75" TP_H045P075 2418.88,514.41 r90 top
TP23 "DAC_OUT" TP_H045P075 2640.68,516.52 r90 top
U1 "LM5013QDDARQ1" DDA0008E-MFG 769.28,2621.68 r90 top
U2 "TPS62130AQRGTTQ1" RGT0016C 1849.56,2409.85 r270 top locked
U3 "TPS62130AQRGTTQ1" RGT0016C 2590.39,2409.85 r270 top locked
U4 "LM3671TLX-1.8/NOPB" YZR0005AEBA 3229.8,2270.72 r0 top locked
U5 "TPS92515QDGQRQ1" DGQ0010E_N 3862.94,1866.11 r180 top locked
U6 "SN74LVC2G08IDCTRQ1" DCT0008A_N 1792.76,1602.82 r0 top locked
U7 "S25FL128SAGNFV003" FP-S25FL128SAGNFI000_WSON8-MFG 2292.46,1468.98 r180 top locked
U8 "TPS389001QDSERQ1" DSE0006A 1472.07,1448.8 r0 top locked
U9 "TPS65100QPWPRQ1" PWP0024B_NV_L 4228.13,1293.29 r180 top locked
U10 "SN74AHC1G32TDBVRQ1" DBV0005A_N 1768.18,1352.07 r0 top locked
U11 "TPS3703E4080DSERQ1" DSE0006A 1490.93,1243.72 r90 top locked
U12 "XAM2634AOLFGMZCZQ" ZCZ0324A-MFG 2754.8,863.44 r0 top locked
U13 "SN74AXC8T245RHLR" RHL0024A 3447.07,977.29 r0 top locked
U14 "SN74AHC1G04QDBVRQ1" DBV0005A_N 4114.78,983.88 r0 top locked
U15 "MTFC8GAMALNA-AAT" FP-MTFC128GAPALNA-AAT_TBGA100-MFG 1511.83,694.3 r0 top locked
U16 "SN74AXC8T245RHLR" RHL0024A 3447.07,559.8 r0 top locked
U17 "SN74LVC1G14QDCKRQ1" DCK0005A_N 588.87,527.54 r270 top locked
U18 "TXU0104BQAR" BQA0014A-MFG 587.58,351.41 r180 top locked
U19 "SN74AXC2T245RSW" RSW0010A 3447.11,273.55 r0 top locked
U20 "TS5A3357QDCURQ1" DCU0008A_N 3452.42,1550.68 r0 top
U21 "TMP411AQDGKRQ1" DGK0008A_N 4517.24,437.66 r0 top
U22 "TPS3840DL47DBVRQ1" DBV0005A_N 1875.94,1804.15 r270 top
Y1 "ECS-2520S18-250-FN-TR" ECS_ECS-2520S 2301.82,630.17 r90 top locked
ZZ1 "This Assembly Note is for PCB labels only" AssemblyNoteLabel -91.1,3493.61 r0 top locked
ZZ2 "These assemblies are ESD sensitive, ESD precautions shall be observed." AssemblyNote -91.1,3384.72 r0 top locked
ZZ3 "These assemblies must be clean and free from flux and all contaminants. Use of no clean flux is not acceptable." AssemblyNote -91.1,3296.17 r0 top locked
ZZ4 "These assemblies must comply with workmanship standards IPC-A-610 Class 2, unless otherwise specified." AssemblyNote -91.1,3207.61 r0 top locked
ZZ5 "Indication provided for the D* components at their cathode side." AssemblyNote -91.29,3108.68 r0 top locked

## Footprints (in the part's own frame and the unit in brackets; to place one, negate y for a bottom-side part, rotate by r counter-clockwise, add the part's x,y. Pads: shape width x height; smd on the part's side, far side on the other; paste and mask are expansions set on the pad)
0201#1 [mm] "Data from Kemet datasheet CC101_COM dated 7/28/11"
  rect 0.46x0.42 smd mask+0: 1(-0.33,0) 2(0.33,0)
0201#2 [mm] "Data from Kemet datasheet CC101_COM dated 7/28/11"
  rect 0.46x0.42 smd mask+0.048: 1(-0.33,0) 2(0.33,0)
0201#3 [mm] "Data from Kemet datasheet CC101_COM dated 7/28/11"
  rect 0.46x0.42 smd: 1(-0.33,0) 2(0.33,0)
0201_033#1 [mm] "SMD, 2-Leads, Height 0.33mm"
  rect 0.46x0.42 smd mask+0: 1(-0.33,0) 2(0.33,0)
0201_033#2 [mm] "SMD, 2-Leads, Height 0.33mm"
  rect 0.46x0.42 smd: 1(-0.33,0) 2(0.33,0)
0402 [mm] "0402 from SM-752 data"
  rect 0.8x0.6 smd: 1(-0.6,0) 2(0.6,0)
  silkscreen extent -1.22,-0.52 1.22,0.52
0402L [mm] "0402 from SM-752 data"
  rect 0.6x0.5 smd: 1(-0.5,0) 2(0.5,0)
571-0100 [mm] "Deltron Emcon recommended land pattern 2003-10-13"
  rect 2.3x2.3 hole 1.8: 1(-7.65,0)
  round 2.3 hole 1.8: 2(7.65,0)
  silkscreen extent -9.74,-5.47 11.09,4.88
571-0500 [mm] "Deltron Emcon recommended land pattern 2003-10-13"
  rect 2.3x2.3 hole 1.8: 1(-7.65,0)
  round 2.3 hole 1.8: 2(7.65,0)
  silkscreen extent -9.74,-5.47 11.09,4.88
0603 [mm] "0603 from SM-752 data"
  rect 1x0.95 smd: 1(-0.8,0) 2(0.8,0)
  silkscreen extent -1.52,-0.69 1.52,0.69
0603L [mm] "0603 from SM-752 data"
  rect 0.8x0.85 smd: 1(-0.7,0) 2(0.7,0)
  silkscreen extent -0.07,-0.33 0.07,0.33
0805_HV [mil] "0805 with 30mil clearance between pads"
  rect 50x63 smd: 1(-40,0) 2(40,0)
  silkscreen extent -74,-40 74,40
0805L [mm] "0805 from SM-752 data"
  rect 1.1x1.4 smd: 1(-0.75,0) 2(0.75,0)
1206 [mm] "1206 from SM-752 data"
  rect 1.3x1.85 smd: 1(-1.45,0) 2(1.45,0)
  silkscreen extent -2.4,-1.21 2.4,1.21
1206_190L [mm] "1206_190"
  rect 1.1x1.75 smd: 1(-1.35,0) 2(1.35,0)
  silkscreen extent -0.4,-0.77 0.4,0.77
1210 [mm] "1210 from SM-752 data"
  rect 1.3x2.7 smd: 1(-1.45,0) 2(1.45,0)
  silkscreen extent -2.32,-1.57 2.32,1.57
AssemblyNote [mil] "Assembly Note"
AssemblyNoteLabel [mil] "Assembly Note for PCB Labels"
BQA0014A-MFG [mm]
  rrect40% 0.25x0.6 smd paste+0 mask+0: 1(-0.25,1.4) 7(-0.25,-1.4) 8(0.25,-1.4) 14(0.25,1.4)
  rrect40% 0.6x0.25 smd paste+0 mask+0: 2(-1.15,1) 3(-1.15,0.5) 4(-1.15,0) 5(-1.15,-0.5) 6(-1.15,-1) 9(1.15,-1) 10(1.15,-0.5) 11(1.15,0) 12(1.15,0.5) 13(1.15,1)
  rrect10% 1x1.5 smd paste-1000 mask+0: 15(0,0)
  silkscreen extent -1.3,-1.55 1.3,2.37
CE_Mark_5mm [mil] "Minimum text height for CE Mark"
